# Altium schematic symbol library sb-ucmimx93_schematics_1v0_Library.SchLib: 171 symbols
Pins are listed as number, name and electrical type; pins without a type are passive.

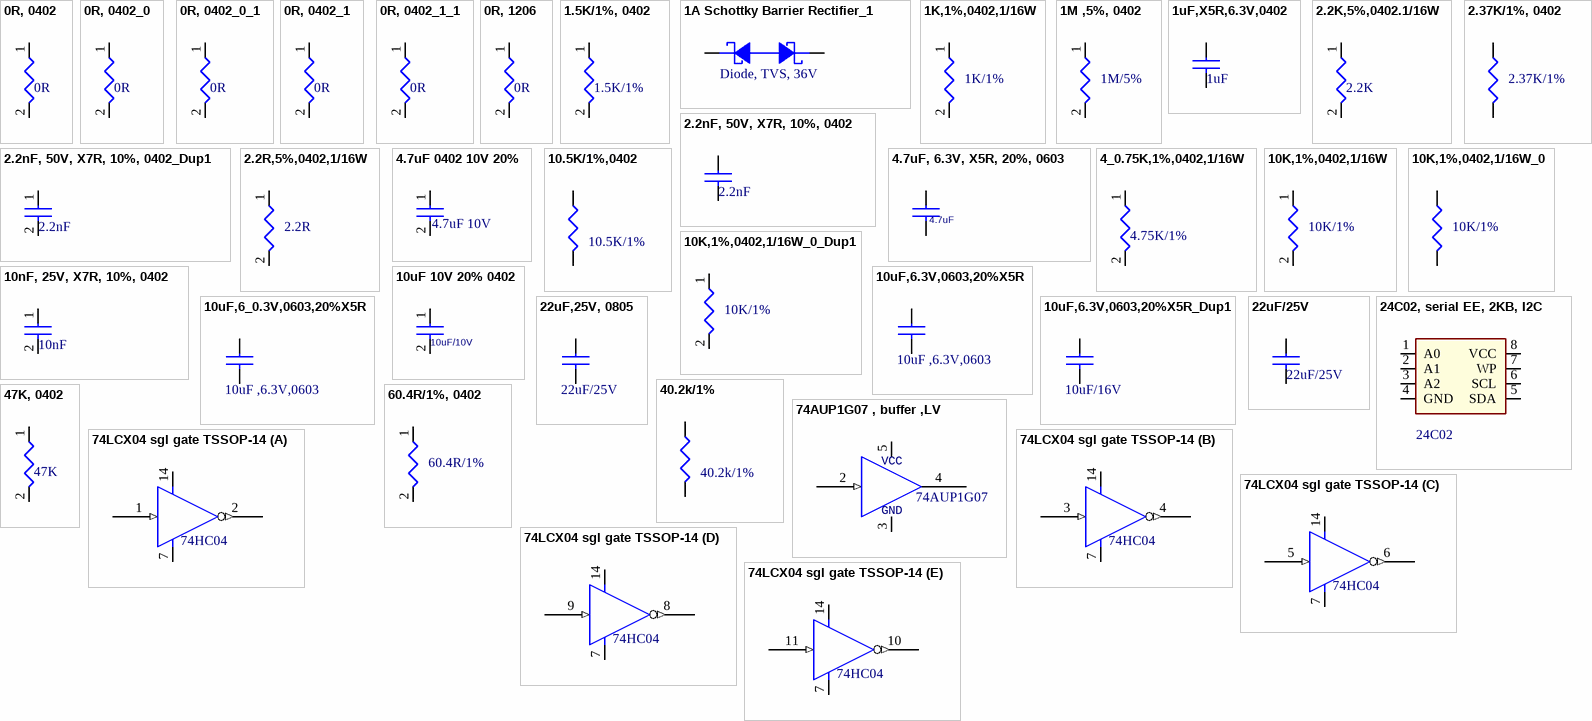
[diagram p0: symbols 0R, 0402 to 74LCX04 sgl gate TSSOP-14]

## 0R, 0402
designator R?, comment 0R
P/N: 161C00005S
footprint RC0402
pins: 1, 2

## 0R, 0402_0
designator R?, comment 0R
P/N: 161C00005S
footprint RC0402
pins: 1, 2

## 0R, 0402_0_1
designator R?, comment 0R
P/N: 161C00005S
footprint RC0402
pins: 1, 2

## 0R, 0402_1
designator R?, comment 0R
P/N: 161C00005S
footprint RC0402
pins: 1, 2

## 0R, 0402_1_1
designator R?, comment 0R
P/N: 161C00005S
footprint RC0402
pins: 1, 2

## 0R, 1206
designator R?, comment 0R
P/N: 161F00005S
footprint RC1206
pins: 1, 2

## 1.5K/1%, 0402
designator R?, comment 1.5K/1%
P/N: 161C15011S
footprint RC0402
pins: 1, 2

## 1A Schottky Barrier Rectifier_1
designator D?, comment Diode, TVS, 36V
P/N: 130E13000S
footprint SOD-123
pins: ANODE, CATHODE

## 1K,1%,0402,1/16W
designator R?, comment 1K/1%
P/N: 161C10011S
footprint RC0402
pins: 1, 2

## 1M ,5%, 0402
designator R?, comment 1M/5%
P/N: 161C10045S
pins: 1, 2

## 1uF,X5R,6.3V,0402
designator C?, comment 1uF
P/N: 151B10500S
footprint RC0402
pins: 1, 2

## 2.2K,5%,0402.1/16W
designator R?, comment 2.2K
P/N: 161C22015S
pins: 1, 2

## 2.2nF, 50V, X7R, 10%, 0402
designator C?, comment 2.2nF
P/N: 151D22200S
footprint RC0402
pins: 1, 2

## 2.2nF, 50V, X7R, 10%, 0402_Dup1
designator C?, comment 2.2nF
P/N: 151D22200S
footprint RC0402
pins: 1, 2

## 2.2R,5%,0402,1/16W
designator R?, comment 2.2R
P/N: 161C2R205S
footprint RC0402
pins: 1, 2

## 2.37K/1%, 0402
designator R?, comment 2.37K/1%
P/N: 161C23711S
footprint RC0402
pins: 1, 2

## 4.7uF 0402 10V 20%
designator C?, comment 4.7uF 10V
P/N: 151B47500S
footprint 0402
pins: 1, 2

## 4.7uF, 6.3V, X5R, 20%, 0603
designator C?, comment 4.7uF
P/N: 151B47510S
footprint C0603-08
pins: 1, 2

## 4_0.75K,1%,0402,1/16W
designator R?, comment 4.75K/1%
P/N: 161C47511S
footprint RC0402
pins: 1, 2

## 10.5K/1%,0402
designator R?, comment 10.5K/1%
P/N: 161C10521S
footprint RC0402
pins: 1, 2

## 10K,1%,0402,1/16W
designator R?, comment 10K/1%
P/N: 161C10021S
footprint RC0402
pins: 1, 2

## 10K,1%,0402,1/16W_0
designator R?, comment 10K/1%
P/N: 161C10021S
footprint RC0402
pins: 1, 2

## 10K,1%,0402,1/16W_0_Dup1
designator R?, comment 10K/1%
P/N: 161C10021S
footprint RC0402
pins: 1, 2

## 10nF, 25V, X7R, 10%, 0402
designator C?, comment 10nF
P/N: 151C10300S
footprint RC0402
pins: 1, 2

## 10uF 10V 20% 0402
designator C?, comment 10uF/10V
OriginalSymbolOrigin: (0,0); P/N: 151B10600S
footprint 0402
pins: 1, 2

## 10uF,6.3V,0603,20%X5R
designator C?, comment 10uF ,6.3V,0603
P/N: 151B10610S
footprint RC0603
pins: 1, 2

## 10uF,6.3V,0603,20%X5R_Dup1
designator C?, comment 10uF/16V
P/N: 151C10610S
footprint RC0603
pins: 1, 2

## 10uF,6_0.3V,0603,20%X5R
designator C?, comment 10uF ,6.3V,0603
P/N: 151B10610S
footprint RC0603
pins: 1, 2

## 22uF,25V, 0805
designator C?, comment 22uF/25V
P/N: 151C22620S
footprint C0805
pins: 1, 2

## 22uF/25V
designator C?
P/N: 151C22620S
footprint C0805
pins: 1, 2

## 24C02, serial EE, 2KB, I2C
designator U?, comment 24C02
P/N: 111S30800S
footprint MO-229VCED-2
pins: 1 A0, 2 A1, 3 A2, 4 GND, 5 SDA, 6 SCL, 7 WP, 8 VCC

## 40.2k/1%
designator R?
P/N: 161C40221S
footprint RC0402
pins: 1, 2

## 47K, 0402
designator R?, comment 47K
P/N: 161C47025S
footprint RC0402
pins: 1, 2

## 60.4R/1%, 0402
designator R?, comment 60.4R/1%
P/N: 161C60R41S
footprint RC0402
pins: 1, 2

## 74AUP1G07 , buffer ,LV
designator U?, comment 74AUP1G07
P/N: 106D20071S
footprint SC70
pins: 2 IN (in), 3 GND (power), 4 OUT (oc), 5 VCC (power)

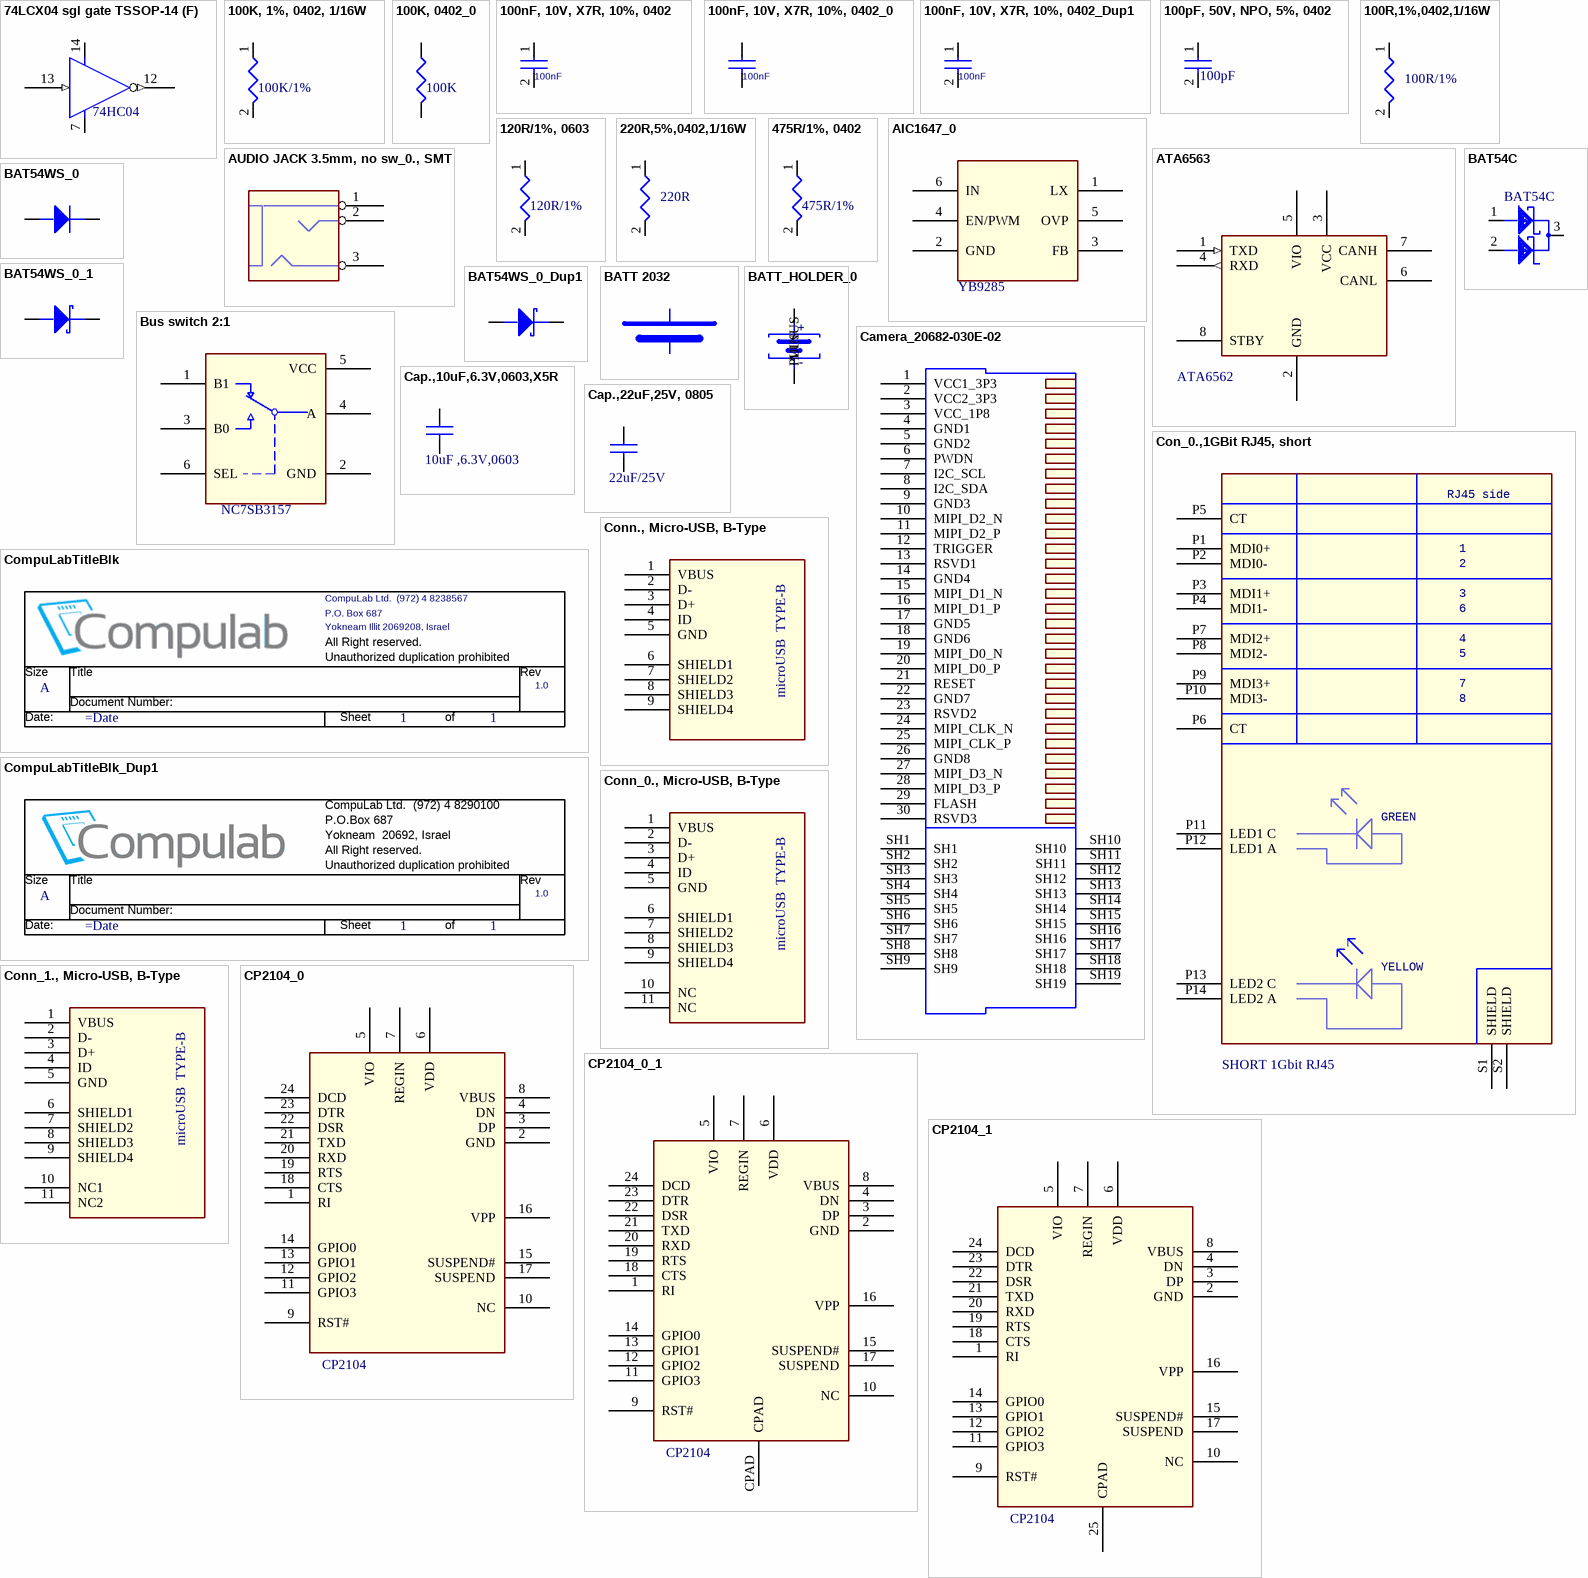
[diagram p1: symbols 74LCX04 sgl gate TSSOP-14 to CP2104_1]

## 74LCX04 sgl gate TSSOP-14
designator U?, comment 74HC04
P/N: 106D30040S
footprint TSSOP-14
part A pins: 1 I (in), 2 12 (out), 7 GND (power), 14 VCC (power)
part B pins: 3 I (in), 4 12 (out), 7 GND (power), 14 VCC (power)
part C pins: 5 I (in), 6 12 (out), 7 GND (power), 14 VCC (power)
part D pins: 7 GND (power), 8 12 (out), 9 I (in), 14 VCC (power)
part E pins: 7 GND (power), 10 12 (out), 11 I (in), 14 VCC (power)
part F pins: 7 GND (power), 12 (out), 13 I (in), 14 VCC (power)
1 alternate drawing of the same symbol

## 100K, 1%, 0402, 1/16W
designator R?, comment 100K/1%
P/N: 161C10031S
footprint RC0402
pins: 1, 2

## 100K, 0402_0
designator R?, comment 100K
P/N: 161C10035S
footprint RC0402
pins: 1, 2

## 100nF, 10V, X7R, 10%, 0402
designator C?, comment 100nF
P/N: 151B10400S
footprint RC0402
pins: 1, 2

## 100nF, 10V, X7R, 10%, 0402_0
designator C?, comment 100nF
P/N: 151B10400S
footprint RC0402
pins: 1, 2

## 100nF, 10V, X7R, 10%, 0402_Dup1
designator C?, comment 100nF
P/N: 151B10400S
footprint RC0402
pins: 1, 2

## 100pF, 50V, NPO, 5%, 0402
designator C?, comment 100pF
P/N: 151D10100S
footprint RC0402
pins: 1, 2

## 100R,1%,0402,1/16W
designator R?, comment 100R/1%
P/N: 161C10001S
footprint RC0402
pins: 1, 2

## 120R/1%, 0603
designator R?, comment 120R/1%
P/N: 161D12001S
footprint RC0603
pins: 1, 2

## 220R,5%,0402,1/16W
designator R?, comment 220R
P/N: 161C22005S
footprint RC0402
pins: 1, 2

## 475R/1%, 0402
designator R?, comment 475R/1%
P/N: 161C47501S
footprint RC0402
pins: 1, 2

## AIC1647_0
designator U?, comment YB9285
P/N: 123C20000S
footprint SOT23-5
pins: 1 LX, 2 GND, 3 FB, 4 EN/PWM, 5 OVP, 6 IN

## ATA6563
designator U?, comment ATA6562
P/N: 116A10500S
pins: 1 TXD (in), 2 GND (power), 3 VCC (power), 4 RXD (out), 5 VIO (power), 6 CANL, 7 CANH, 8 STBY

## AUDIO JACK 3.5mm, no sw_0., SMT
designator J?
P/N: 182K00300S
footprint AJ35-3P-SM
pins: 1 COM, 2 L, 3 R

## BAT54C
designator D?
P/N: 130E05400S
footprint SOT23
pins: 1 ANODE1, 2 ANODE2, 3 CATHODE

## BAT54WS_0
designator D?
P/N: 130E05402S
footprint SOD-323
pins: ANODE, CATHODE

## BAT54WS_0_1
designator D?
P/N: 130E05402S
footprint SOD-323
pins: ANODE, CATHODE

## BAT54WS_0_Dup1
designator D?
P/N: 130E05402S
footprint SOD-323
pins: ANODE, CATHODE

## BATT 2032
designator BT?
P/N: 210C30002

## BATT_HOLDER_0
designator BH?
P/N: 190Z00201
footprint BATTH20MM
pins: 1 MINUS, 2 PLUS

## Bus switch 2:1
designator U?, comment NC7SB3157
P/N: 124S10050S
footprint SC70-6
pins: 1 B1, 2 GND, 3 B0, 4 A, 5 VCC, 6 SEL

## Camera_20682-030E-02
designator P?
P/N: 182P04000S
pins: 1 VCC1_3P3, 2 VCC2_3P3, 3 VCC_1P8, 4 GND1, 5 GND2, 6 PWDN, 7 I2C_SCL, 8 I2C_SDA, 9 GND3, 10 MIPI_D2_N, 11 MIPI_D2_P, 12 TRIGGER, 13 RSVD1, 14 GND4, 15 MIPI_D1_N, 16 MIPI_D1_P, 17 GND5, 18 GND6, 19 MIPI_D0_N, 20 MIPI_D0_P, 21 RESET, 22 GND7, 23 RSVD2, 24 MIPI_CLK_N, 25 MIPI_CLK_P, 26 GND8, 27 MIPI_D3_N, 28 MIPI_D3_P, 29 FLASH, 30 RSVD3, SH1, SH2, SH3, SH4, SH5, SH6, SH7, SH8, SH9, SH10, SH11, SH12, SH13, SH14, SH15, SH16, SH17, SH18, SH19

## Cap.,10uF,6.3V,0603,X5R
designator C?, comment 10uF ,6.3V,0603
P/N: 151B10610S
footprint RC0603
pins: 1, 2

## Cap.,22uF,25V, 0805
designator C?, comment 22uF/25V
P/N: 151C22620S
footprint C0805
pins: 1, 2

## CompuLabTitleBlk
designator *  RevCode: 1.0  OrgName: CompuLab Ltd.  (972) 4 8238567  OrgAddr1: P.O. Box 687  OrgAddr2: Yokneam Illit 2069208, Israel  Page Size: A  Page Number: 1  (hidden comment: *)  (graphical)

## CompuLabTitleBlk_Dup1
designator *  RevCode: 1.0  Page Size: A  Page Number: 1  (hidden comment: *)  (graphical)
OrgName: CompuLab Ltd.  (972) 4 8238567; OrgAddr1: P.O.Box 66; OrgAddr2: Nesher 36770, Israel

## Con_0.,1GBit RJ45, short
designator P?, comment SHORT 1Gbit RJ45
P/N: 182K01600
footprint RJTR1GRATH
pins: P1 MDI0+, P2 MDI0-, P3 MDI1+, P4 MDI1-, P5 CT, P6 CT, P7 MDI2+, P8 MDI2-, P9 MDI3+, P10 MDI3-, P11 LED1 C, P12 LED1 A, P13 LED2 C, P14 LED2 A, S1 SHIELD (power), S2 SHIELD (power)

## Conn., Micro-USB, B-Type
designator P?, comment microUSB  TYPE-B
P/N: 180K00501S
footprint MICRO-USB-B-RA-SM
pins: 1 VBUS, 2 D-, 3 D+, 4 ID, 5 GND, 6 SHIELD1, 7 SHIELD2, 8 SHIELD3, 9 SHIELD4

## Conn_0., Micro-USB, B-Type
designator P?, comment microUSB  TYPE-B
P/N: 180K00501S
footprint MICRO-USB-B-RA-SM
pins: 1 VBUS, 2 D-, 3 D+, 4 ID, 5 GND, 6 SHIELD1, 7 SHIELD2, 8 SHIELD3, 9 SHIELD4, 10 NC, 11 NC

## Conn_1., Micro-USB, B-Type
designator P?, comment microUSB  TYPE-B
P/N: 180K00501S
footprint MICRO-USB-B-RA-SM
pins: 1 VBUS, 2 D-, 3 D+, 4 ID, 5 GND, 6 SHIELD1, 7 SHIELD2, 8 SHIELD3, 9 SHIELD4, 10 NC1, 11 NC2

## CP2104_0
designator U?, comment CP2104
pins: 1 RI, 2 GND, 3 DP, 4 DN, 5 VIO, 6 VDD, 7 REGIN, 8 VBUS, 9 RST#, 10 NC, 11 GPIO3, 12 GPIO2, 13 GPIO1, 14 GPIO0, 15 SUSPEND#, 16 VPP, 17 SUSPEND, 18 CTS, 19 RTS, 20 RXD, 21 TXD, 22 DSR, 23 DTR, 24 DCD

## CP2104_0_1
designator U?, comment CP2104
pins: 1 RI, 2 GND, 3 DP, 4 DN, 5 VIO, 6 VDD, 7 REGIN, 8 VBUS, 9 RST#, 10 NC, 11 GPIO3, 12 GPIO2, 13 GPIO1, 14 GPIO0, 15 SUSPEND#, 16 VPP, 17 SUSPEND, 18 CTS, 19 RTS, 20 RXD, 21 TXD, 22 DSR, 23 DTR, 24 DCD, CPAD

## CP2104_1
designator U?, comment CP2104
pins: 1 RI, 2 GND, 3 DP, 4 DN, 5 VIO, 6 VDD, 7 REGIN, 8 VBUS, 9 RST#, 10 NC, 11 GPIO3, 12 GPIO2, 13 GPIO1, 14 GPIO0, 15 SUSPEND#, 16 VPP, 17 SUSPEND, 18 CTS, 19 RTS, 20 RXD, 21 TXD, 22 DSR, 23 DTR, 24 DCD, 25 CPAD

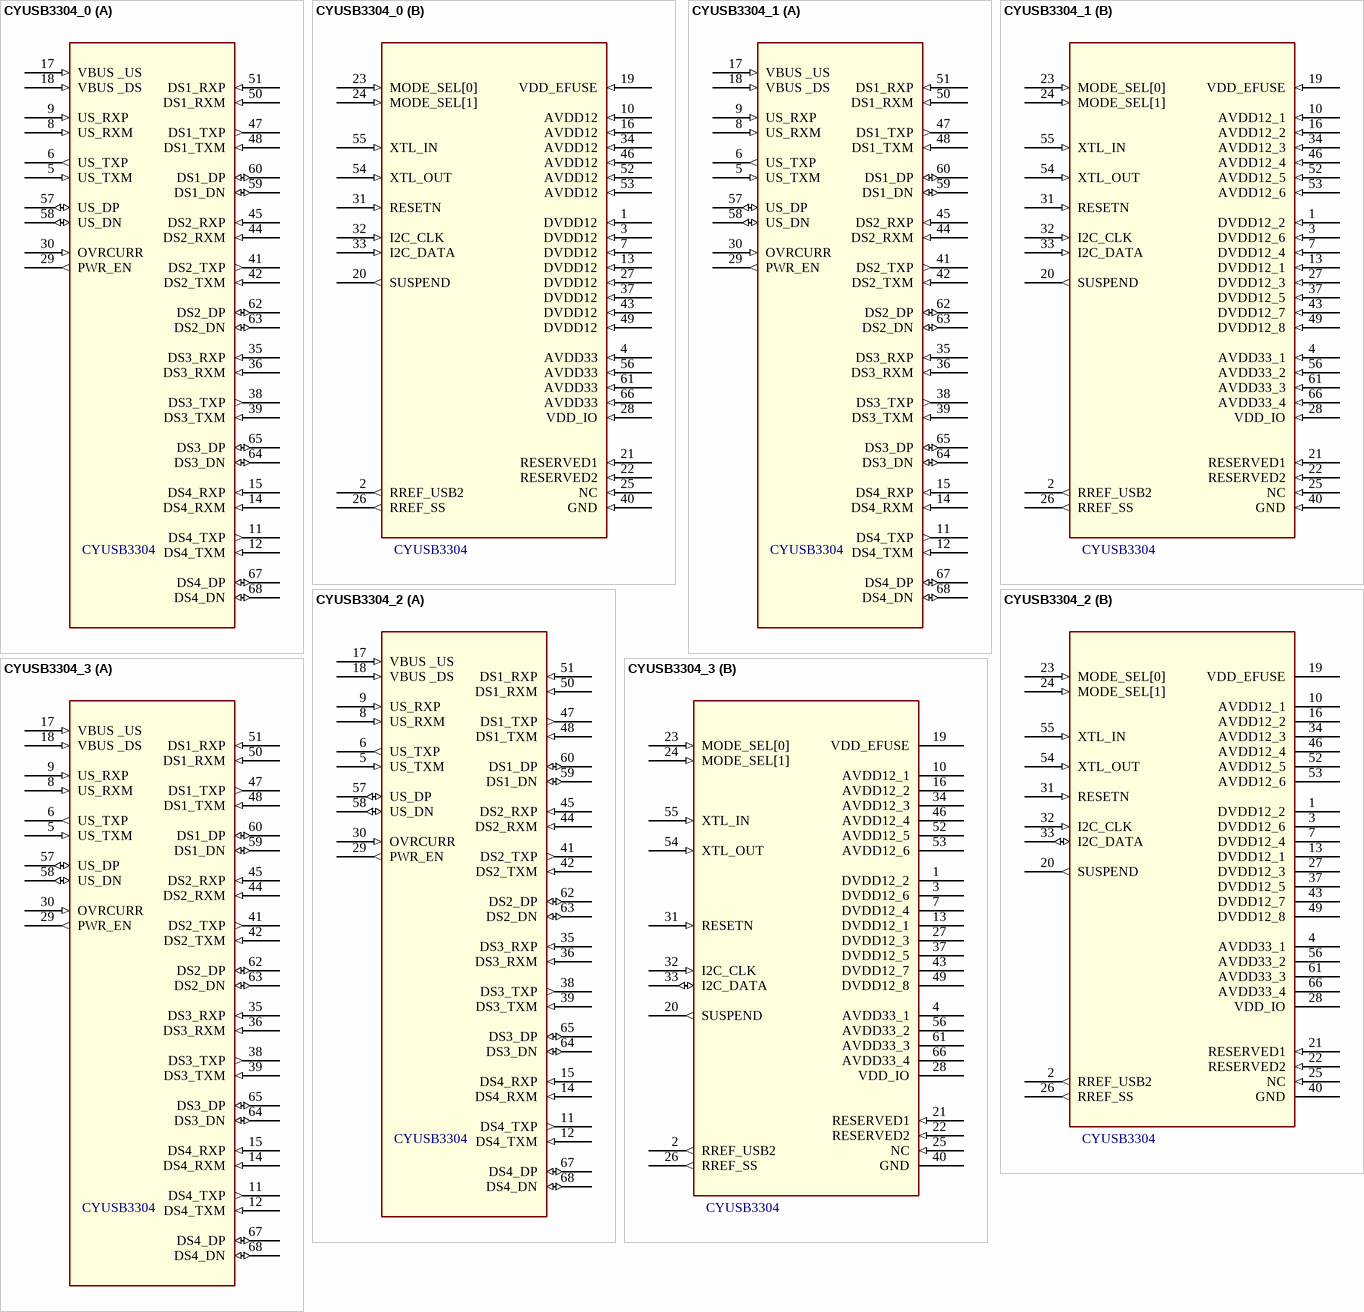
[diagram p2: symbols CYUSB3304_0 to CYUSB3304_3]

## CYUSB3304_0
designator U?, comment CYUSB3304
part A pins: 5 US_TXM (in), 6 US_TXP (out), 8 US_RXM (in), 9 US_RXP (in), 11 DS4_TXP (out), 12 DS4_TXM (in), 14 DS4_RXM (in), 15 DS4_RXP (in), 17 VBUS _US (in), 18 VBUS _DS (in), 29 PWR_EN (out), 30 OVRCURR (in), 35 DS3_RXP (in), 36 DS3_RXM (in), 38 DS3_TXP (out), 39 DS3_TXM (in), 41 DS2_TXP (out), 42 DS2_TXM (in), 44 DS2_RXM (in), 45 DS2_RXP (in), 47 DS1_TXP (out), 48 DS1_TXM (in), 50 DS1_RXM (in), 51 DS1_RXP (in), 57 US_DP (io), 58 US_DN (io), 59 DS1_DN (io), 60 DS1_DP (io), 62 DS2_DP (io), 63 DS2_DN (io), 64 DS3_DN (io), 65 DS3_DP (io), 67 DS4_DP (io), 68 DS4_DN (io)
part B pins: 1 DVDD12 (in), 2 RREF_USB2 (out), 3 DVDD12 (in), 4 AVDD33 (in), 7 DVDD12 (in), 10 AVDD12 (in), 13 DVDD12 (in), 16 AVDD12 (in), 19 VDD_EFUSE (in), 20 SUSPEND (out), 21 RESERVED1 (in), 22 RESERVED2 (in), 23 MODE_SEL[0] (in), 24 MODE_SEL[1] (in), 25 NC (in), 26 RREF_SS (out), 27 DVDD12 (in), 28 VDD_IO (in), 31 RESETN (in), 32 I2C_CLK (in), 33 I2C_DATA (in), 34 AVDD12 (in), 37 DVDD12 (in), 40 GND (in), 43 DVDD12 (in), 46 AVDD12 (in), 49 DVDD12 (in), 52 AVDD12 (in), 53 AVDD12 (in), 54 XTL_OUT (in), 55 XTL_IN (in), 56 AVDD33 (in), 61 AVDD33 (in), 66 AVDD33 (in)

## CYUSB3304_1
designator U?, comment CYUSB3304
part A pins: 5 US_TXM (in), 6 US_TXP (out), 8 US_RXM (in), 9 US_RXP (in), 11 DS4_TXP (out), 12 DS4_TXM (in), 14 DS4_RXM (in), 15 DS4_RXP (in), 17 VBUS _US (in), 18 VBUS _DS (in), 29 PWR_EN (out), 30 OVRCURR (in), 35 DS3_RXP (in), 36 DS3_RXM (in), 38 DS3_TXP (out), 39 DS3_TXM (in), 41 DS2_TXP (out), 42 DS2_TXM (in), 44 DS2_RXM (in), 45 DS2_RXP (in), 47 DS1_TXP (out), 48 DS1_TXM (in), 50 DS1_RXM (in), 51 DS1_RXP (in), 57 US_DP (io), 58 US_DN (io), 59 DS1_DN (io), 60 DS1_DP (io), 62 DS2_DP (io), 63 DS2_DN (io), 64 DS3_DN (io), 65 DS3_DP (io), 67 DS4_DP (io), 68 DS4_DN (io)
part B pins: 1 DVDD12_2 (in), 2 RREF_USB2 (out), 3 DVDD12_6 (in), 4 AVDD33_1 (in), 7 DVDD12_4 (in), 10 AVDD12_1 (in), 13 DVDD12_1 (in), 16 AVDD12_2 (in), 19 VDD_EFUSE (in), 20 SUSPEND (out), 21 RESERVED1 (in), 22 RESERVED2 (in), 23 MODE_SEL[0] (in), 24 MODE_SEL[1] (in), 25 NC (in), 26 RREF_SS (out), 27 DVDD12_3 (in), 28 VDD_IO (in), 31 RESETN (in), 32 I2C_CLK (in), 33 I2C_DATA (in), 34 AVDD12_3 (in), 37 DVDD12_5 (in), 40 GND (in), 43 DVDD12_7 (in), 46 AVDD12_4 (in), 49 DVDD12_8 (in), 52 AVDD12_5 (in), 53 AVDD12_6 (in), 54 XTL_OUT (in), 55 XTL_IN (in), 56 AVDD33_2 (in), 61 AVDD33_3 (in), 66 AVDD33_4 (in)

## CYUSB3304_2
designator U?, comment CYUSB3304
part A pins: 5 US_TXM (in), 6 US_TXP (out), 8 US_RXM (in), 9 US_RXP (in), 11 DS4_TXP (out), 12 DS4_TXM (in), 14 DS4_RXM (in), 15 DS4_RXP (in), 17 VBUS _US (in), 18 VBUS _DS (in), 29 PWR_EN (out), 30 OVRCURR (in), 35 DS3_RXP (in), 36 DS3_RXM (in), 38 DS3_TXP (out), 39 DS3_TXM (in), 41 DS2_TXP (out), 42 DS2_TXM (in), 44 DS2_RXM (in), 45 DS2_RXP (in), 47 DS1_TXP (out), 48 DS1_TXM (in), 50 DS1_RXM (in), 51 DS1_RXP (in), 57 US_DP (io), 58 US_DN (io), 59 DS1_DN (io), 60 DS1_DP (io), 62 DS2_DP (io), 63 DS2_DN (io), 64 DS3_DN (io), 65 DS3_DP (io), 67 DS4_DP (io), 68 DS4_DN (io)
part B pins: 1 DVDD12_2 (power), 2 RREF_USB2 (out), 3 DVDD12_6 (power), 4 AVDD33_1 (power), 7 DVDD12_4 (power), 10 AVDD12_1 (power), 13 DVDD12_1 (power), 16 AVDD12_2 (power), 19 VDD_EFUSE (power), 20 SUSPEND (out), 21 RESERVED1 (in), 22 RESERVED2 (in), 23 MODE_SEL[0] (in), 24 MODE_SEL[1] (in), 25 NC (in), 26 RREF_SS (out), 27 DVDD12_3 (power), 28 VDD_IO (power), 31 RESETN (in), 32 I2C_CLK (in), 33 I2C_DATA (io), 34 AVDD12_3 (power), 37 DVDD12_5 (power), 40 GND (power), 43 DVDD12_7 (power), 46 AVDD12_4 (power), 49 DVDD12_8 (power), 52 AVDD12_5 (power), 53 AVDD12_6 (power), 54 XTL_OUT (in), 55 XTL_IN (in), 56 AVDD33_2 (power), 61 AVDD33_3 (power), 66 AVDD33_4 (power)

## CYUSB3304_3
designator U?, comment CYUSB3304
part A pins: 5 US_TXM (in), 6 US_TXP (out), 8 US_RXM (in), 9 US_RXP (in), 11 DS4_TXP (out), 12 DS4_TXM (in), 14 DS4_RXM (in), 15 DS4_RXP (in), 17 VBUS _US (in), 18 VBUS _DS (in), 29 PWR_EN (out), 30 OVRCURR (in), 35 DS3_RXP (in), 36 DS3_RXM (in), 38 DS3_TXP (out), 39 DS3_TXM (in), 41 DS2_TXP (out), 42 DS2_TXM (in), 44 DS2_RXM (in), 45 DS2_RXP (in), 47 DS1_TXP (out), 48 DS1_TXM (in), 50 DS1_RXM (in), 51 DS1_RXP (in), 57 US_DP (io), 58 US_DN (io), 59 DS1_DN (io), 60 DS1_DP (io), 62 DS2_DP (io), 63 DS2_DN (io), 64 DS3_DN (io), 65 DS3_DP (io), 67 DS4_DP (io), 68 DS4_DN (io)
part B pins: 1 DVDD12_2 (power), 2 RREF_USB2 (out), 3 DVDD12_6 (power), 4 AVDD33_1 (power), 7 DVDD12_4 (power), 10 AVDD12_1 (power), 13 DVDD12_1 (power), 16 AVDD12_2 (power), 19 VDD_EFUSE (power), 20 SUSPEND (out), 21 RESERVED1 (in), 22 RESERVED2 (in), 23 MODE_SEL[0] (in), 24 MODE_SEL[1] (in), 25 NC (in), 26 RREF_SS (out), 27 DVDD12_3 (power), 28 VDD_IO (power), 31 RESETN (in), 32 I2C_CLK (in), 33 I2C_DATA (io), 34 AVDD12_3 (power), 37 DVDD12_5 (power), 40 GND (power), 43 DVDD12_7 (power), 46 AVDD12_4 (power), 49 DVDD12_8 (power), 52 AVDD12_5 (power), 53 AVDD12_6 (power), 54 XTL_OUT (in), 55 XTL_IN (in), 56 AVDD33_2 (power), 61 AVDD33_3 (power), 66 AVDD33_4 (power)

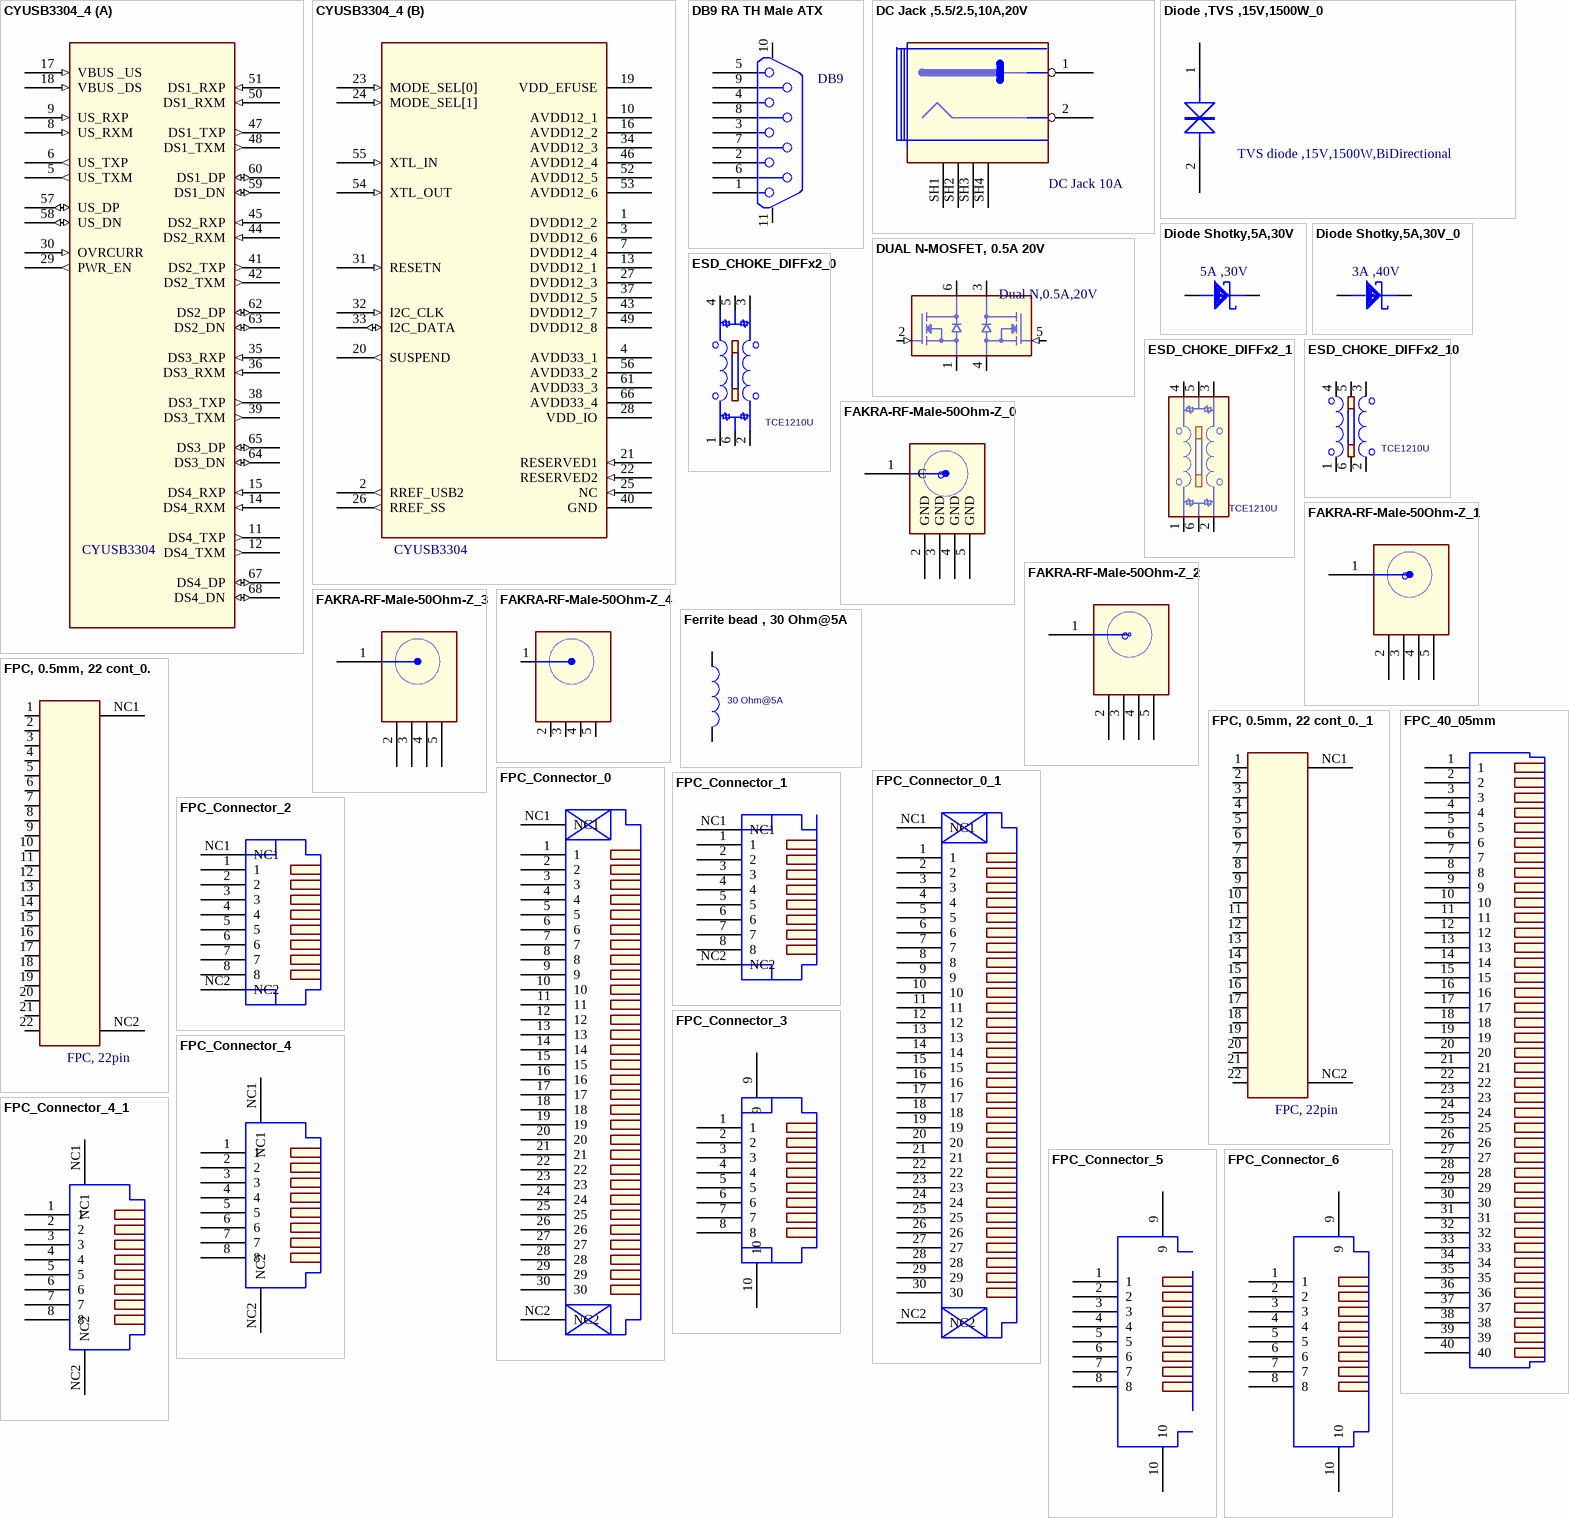
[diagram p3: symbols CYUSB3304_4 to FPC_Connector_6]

## CYUSB3304_4
designator U?, comment CYUSB3304
part A pins: 5 US_TXM (out), 6 US_TXP (out), 8 US_RXM (in), 9 US_RXP (in), 11 DS4_TXP (out), 12 DS4_TXM (out), 14 DS4_RXM (in), 15 DS4_RXP (in), 17 VBUS _US (in), 18 VBUS _DS (in), 29 PWR_EN (out), 30 OVRCURR (in), 35 DS3_RXP (in), 36 DS3_RXM (in), 38 DS3_TXP (out), 39 DS3_TXM (out), 41 DS2_TXP (out), 42 DS2_TXM (out), 44 DS2_RXM (in), 45 DS2_RXP (in), 47 DS1_TXP (out), 48 DS1_TXM (out), 50 DS1_RXM (in), 51 DS1_RXP (in), 57 US_DP (io), 58 US_DN (io), 59 DS1_DN (io), 60 DS1_DP (io), 62 DS2_DP (io), 63 DS2_DN (io), 64 DS3_DN (io), 65 DS3_DP (io), 67 DS4_DP (io), 68 DS4_DN (io)
part B pins: 1 DVDD12_2 (power), 2 RREF_USB2 (out), 3 DVDD12_6 (power), 4 AVDD33_1 (power), 7 DVDD12_4 (power), 10 AVDD12_1 (power), 13 DVDD12_1 (power), 16 AVDD12_2 (power), 19 VDD_EFUSE (power), 20 SUSPEND (out), 21 RESERVED1 (in), 22 RESERVED2 (in), 23 MODE_SEL[0] (in), 24 MODE_SEL[1] (in), 25 NC (in), 26 RREF_SS (out), 27 DVDD12_3 (power), 28 VDD_IO (power), 31 RESETN (in), 32 I2C_CLK (in), 33 I2C_DATA (io), 34 AVDD12_3 (power), 37 DVDD12_5 (power), 40 GND (power), 43 DVDD12_7 (power), 46 AVDD12_4 (power), 49 DVDD12_8 (power), 52 AVDD12_5 (power), 53 AVDD12_6 (power), 54 XTL_OUT (in), 55 XTL_IN (in), 56 AVDD33_2 (power), 61 AVDD33_3 (power), 66 AVDD33_4 (power)

## DB9 RA TH Male ATX
designator P?, comment DB9
P/N: 180K00901
footprint DB9RATH
pins: 1, 2, 3, 4, 5, 6, 7, 8, 9, 10 BRACKET, 11 BRACKET

## DC Jack ,5.5/2.5,10A,20V
designator J?, comment DC Jack 10A
P/N: 180K00200
footprint PJ-0810-TH
pins: 1 CENTRAL, 2 R, SH1, SH2, SH3, SH4

## Diode ,TVS ,15V,1500W_0
designator D?, comment TVS diode ,15V,1500W,BiDirectional
P/N: TMP_TVS
footprint DO-214AB
pins: 1, 2

## Diode Shotky,5A,30V
designator D?, comment 5A ,30V
P/N: 130E30001S
footprint SOD-128
pins: ANODE, CATHODE

## Diode Shotky,5A,30V_0
designator D?, comment 3A ,40V
P/N: 130E30001S
footprint SOD-128
pins: ANODE, CATHODE

## DUAL N-MOSFET, 0.5A 20V
designator Q?, comment Dual N,0.5A,20V
P/N: 131D31540S
footprint SOT-563-6
pins: 1 S1, 2 G1 (in), 3 D2, 4 S2, 5 G2 (in), 6 D1

## ESD_CHOKE_DIFFx2_0
designator L?, comment TCE1210U
P/N: tmp_ESD_CHOKE
footprint 0805
pins: 1, 2, 3, 4, 5 GND (power), 6 GND (power)

## ESD_CHOKE_DIFFx2_1
designator L?, comment TCE1210U
P/N: tmp_ESD_CHOKE
footprint 0805
pins: 1, 2, 3, 4, 5 GND (power), 6 GND (power)

## ESD_CHOKE_DIFFx2_10
designator L?, comment TCE1210U
P/N: tmp_ESD_CHOKE
footprint 0805
pins: 1, 2, 3, 4, 5 GND (power), 6 GND (power)

## FAKRA-RF-Male-50Ohm-Z_0
designator J?
P/N: 182E00402
footprint SMB-JACK
pins: 1 C, 2 GND, 3 GND, 4 GND, 5 GND

## FAKRA-RF-Male-50Ohm-Z_1
designator J?
P/N: 182E00402
footprint SMB-JACK
pins: 1 C, 2 GND, 3 GND, 4 GND, 5 GND

## FAKRA-RF-Male-50Ohm-Z_2
designator J?
P/N: 182E00402
footprint SMB-JACK
pins: 1 C, 2 GND, 3 GND, 4 GND, 5 GND

## FAKRA-RF-Male-50Ohm-Z_3
designator J?
P/N: 182E00402
footprint SMB-JACK
pins: 1 C, 2 GND, 3 GND, 4 GND, 5 GND

## FAKRA-RF-Male-50Ohm-Z_4
designator J?
P/N: 182E00402
footprint SMB-JACK
pins: 1 C, 2 GND, 3 GND, 4 GND, 5 GND

## Ferrite bead , 30 Ohm@5A
designator FB?, comment 30 Ohm@5A
P/N: 147D30000S
footprint FB0603
pins: 1, 2

## FPC, 0.5mm, 22 cont_0.
designator P?, comment FPC, 22pin
P/N: 182P02200S
footprint FPC05SM22
pins: 1, 2, 3, 4, 5, 6, 7, 8, 9, 10, 11, 12, 13, 14, 15, 16, 17, 18, 19, 20, 21, 22, NC1, NC2

## FPC, 0.5mm, 22 cont_0._1
designator P?, comment FPC, 22pin
P/N: 182P02200S
footprint FPC05SM22
pins: 1, 2, 3, 4, 5, 6, 7, 8, 9, 10, 11, 12, 13, 14, 15, 16, 17, 18, 19, 20, 21, 22, NC1, NC2

## FPC_40_05mm
designator P?
P/N: 182P04000S
footprint FPC05SM40
pins: 1, 2, 3, 4, 5, 6, 7, 8, 9, 10, 11, 12, 13, 14, 15, 16, 17, 18, 19, 20, 21, 22, 23, 24, 25, 26, 27, 28, 29, 30, 31, 32, 33, 34, 35, 36, 37, 38, 39, 40

## FPC_Connector_0
designator J?
P/N: 182P04000S
footprint FPC_30
pins: 1, 2, 3, 4, 5, 6, 7, 8, 9, 10, 11, 12, 13, 14, 15, 16, 17, 18, 19, 20, 21, 22, 23, 24, 25, 26, 27, 28, 29, 30, NC1, NC2

## FPC_Connector_0_1
designator J?
P/N: 182P04000S
footprint FPC_30
pins: 1, 2, 3, 4, 5, 6, 7, 8, 9, 10, 11, 12, 13, 14, 15, 16, 17, 18, 19, 20, 21, 22, 23, 24, 25, 26, 27, 28, 29, 30, NC1, NC2

## FPC_Connector_1
designator P?
P/N: 182P04000S
footprint FPC_8
pins: 1, 2, 3, 4, 5, 6, 7, 8, NC1, NC2

## FPC_Connector_2
designator P?
P/N: 182P04000S
footprint FPC_8
pins: 1, 2, 3, 4, 5, 6, 7, 8, NC1, NC2

## FPC_Connector_3
designator P?
P/N: 182P04000S
footprint FPC_8
pins: 1, 2, 3, 4, 5, 6, 7, 8, 9, 10

## FPC_Connector_4
designator P?
P/N: 182P04000S
footprint FPC_8
pins: 1, 2, 3, 4, 5, 6, 7, 8, NC1, NC2

## FPC_Connector_4_1
designator P?
P/N: 182P04000S
footprint FPC_8
pins: 1, 2, 3, 4, 5, 6, 7, 8, NC1, NC2

## FPC_Connector_5
designator P?
P/N: 182P04000S
footprint FPC_8
pins: 1, 2, 3, 4, 5, 6, 7, 8, 9, 10

## FPC_Connector_6
designator P?
P/N: 182P04000S
footprint FPC_8
pins: 1, 2, 3, 4, 5, 6, 7, 8, 9, 10

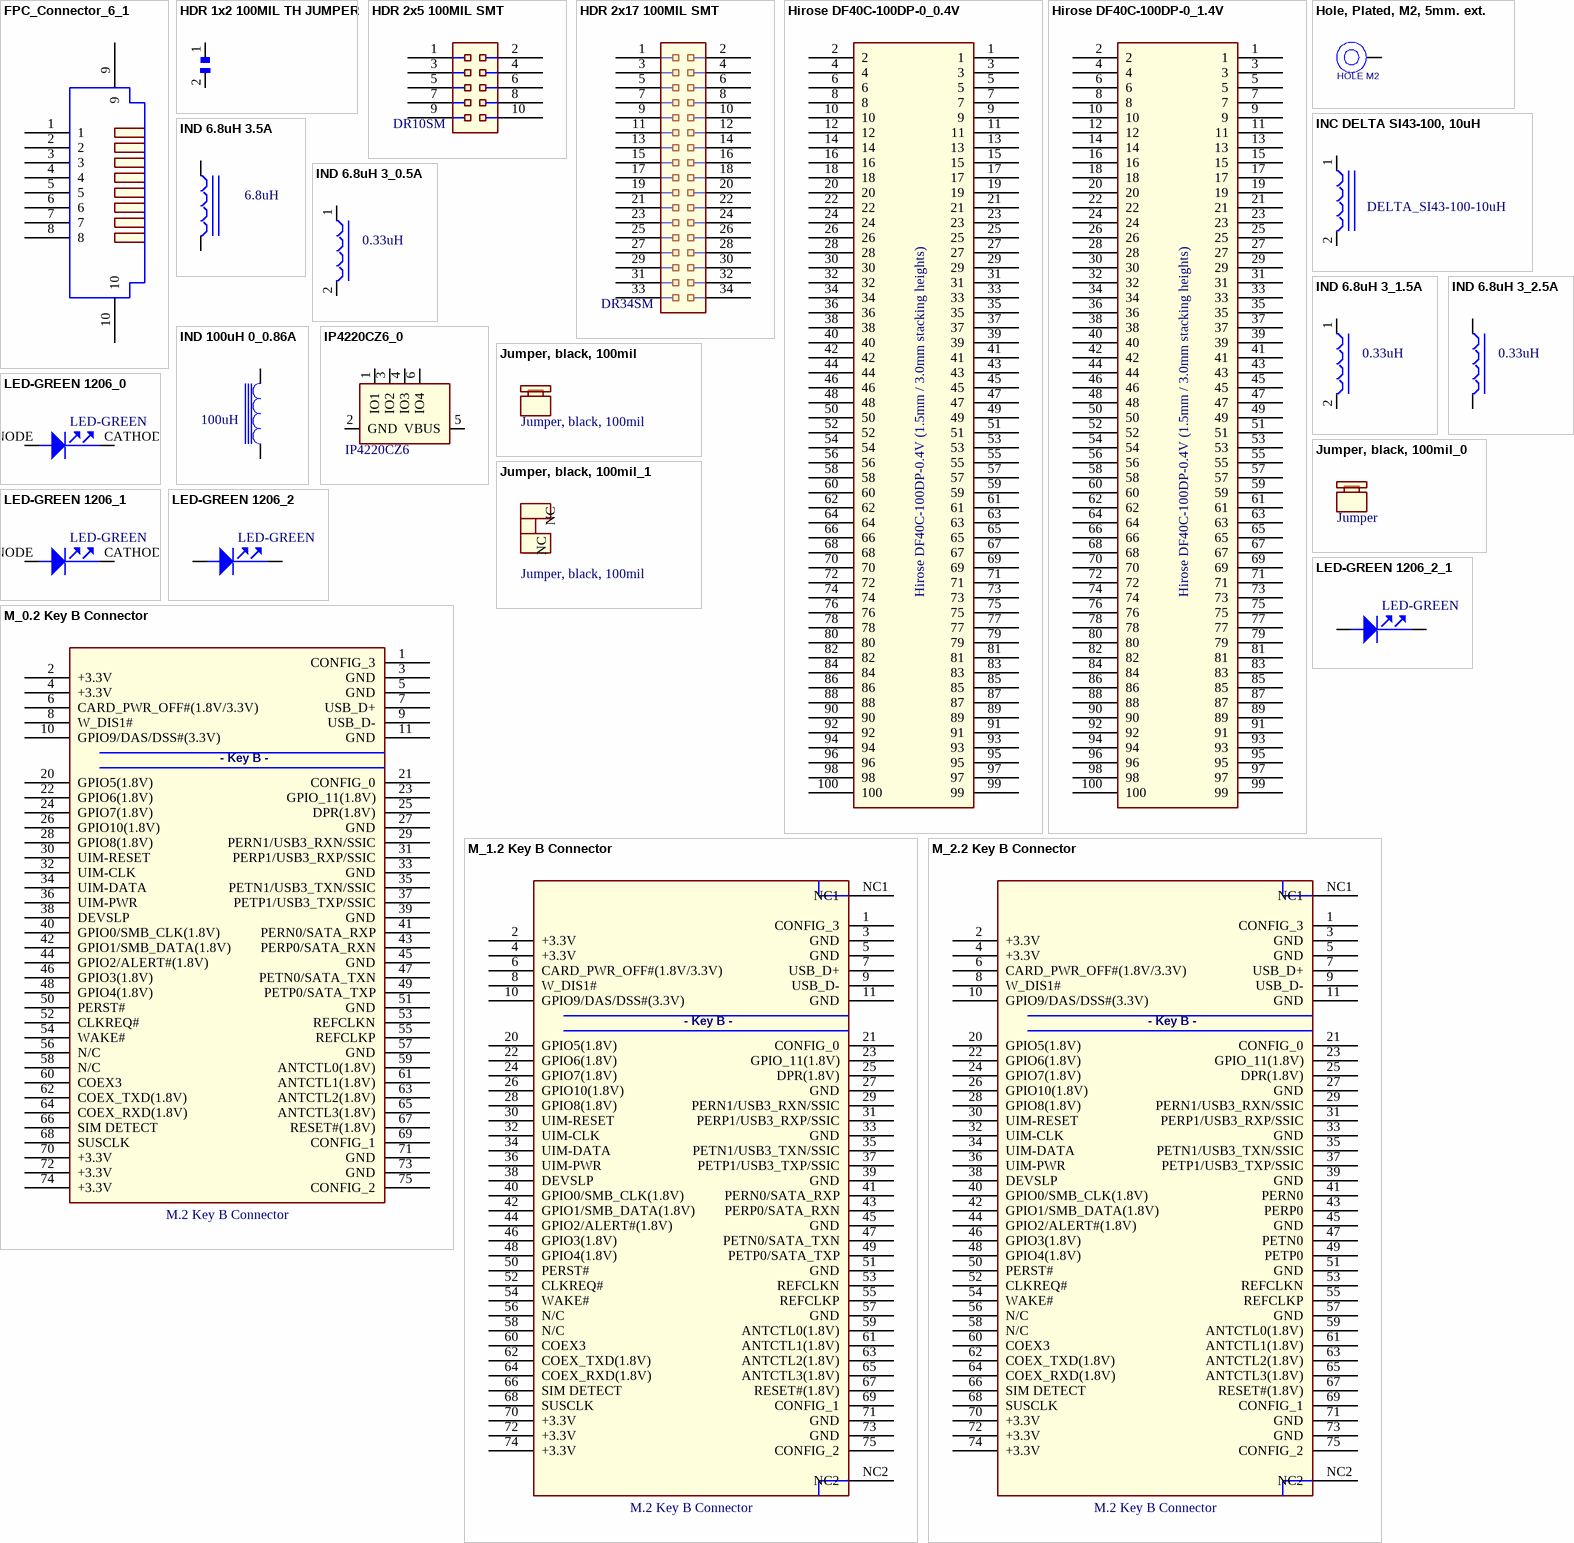
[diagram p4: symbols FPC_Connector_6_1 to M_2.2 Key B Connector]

## FPC_Connector_6_1
designator P?
P/N: 182P04000S
footprint FPC_8
pins: 1, 2, 3, 4, 5, 6, 7, 8, 9, 10

## HDR 1x2 100MIL TH JUMPER
designator E?, comment HDR1X2  (value not drawn)
P/N: 190C00200; PCB Footprint: TH_1x2_100MIL
footprint 1X2THHDR
pins: 1, 2

## HDR 2x5 100MIL SMT
designator P?, comment DR10SM
P/N: 190C01000S
footprint 2X5SMHDR
pins: 1, 2, 3, 4, 5, 6, 7, 8, 9, 10

## HDR 2x17 100MIL SMT
designator P?, comment DR34SM
P/N: 190C03400S
footprint 2X17SMHDR
pins: 1, 2, 3, 4, 5, 6, 7, 8, 9, 10, 11, 12, 13, 14, 15, 16, 17, 18, 19, 20, 21, 22, 23, 24, 25, 26, 27, 28, 29, 30, 31, 32, 33, 34

## Hirose DF40C-100DP-0_0.4V
designator P?, comment Hirose DF40C-100DP-0.4V (1.5mm / 3.0mm stacking heights)
pins: 1, 2, 3, 4, 5, 6, 7, 8, 9, 10, 11, 12, 13, 14, 15, 16, 17, 18, 19, 20, 21, 22, 23, 24, 25, 26, 27, 28, 29, 30, 31, 32, 33, 34, 35, 36, 37, 38, 39, 40, 41, 42, 43, 44, 45, 46, 47, 48, 49, 50, 51, 52, 53, 54, 55, 56, 57, 58, 59, 60, 61, 62, 63, 64, 65, 66, 67, 68, 69, 70, 71, 72, 73, 74, 75, 76, 77, 78, 79, 80, 81, 82, 83, 84, 85, 86, 87, 88, 89, 90, 91, 92, 93, 94, 95, 96, 97, 98, 99, 100

## Hirose DF40C-100DP-0_1.4V
designator P?, comment Hirose DF40C-100DP-0.4V (1.5mm / 3.0mm stacking heights)
pins: 1, 2, 3, 4, 5, 6, 7, 8, 9, 10, 11, 12, 13, 14, 15, 16, 17, 18, 19, 20, 21, 22, 23, 24, 25, 26, 27, 28, 29, 30, 31, 32, 33, 34, 35, 36, 37, 38, 39, 40, 41, 42, 43, 44, 45, 46, 47, 48, 49, 50, 51, 52, 53, 54, 55, 56, 57, 58, 59, 60, 61, 62, 63, 64, 65, 66, 67, 68, 69, 70, 71, 72, 73, 74, 75, 76, 77, 78, 79, 80, 81, 82, 83, 84, 85, 86, 87, 88, 89, 90, 91, 92, 93, 94, 95, 96, 97, 98, 99, 100

## Hole, Plated, M2, 5mm. ext.
designator H?, comment HOLE M2
P/N: 188Z10010
footprint M2PAD
pins: 1

## INC DELTA SI43-100, 10uH
designator L?, comment DELTA_SI43-100-10uH
P/N: 147A10001S
footprint IND4x4x2_5
pins: 1, 2

## IND 6.8uH 3.5A
designator L?, comment 6.8uH
pins: 1, 2

## IND 6.8uH 3_0.5A
designator L?, comment 0.33uH
pins: 1, 2

## IND 6.8uH 3_1.5A
designator L?, comment 0.33uH
pins: 1, 2

## IND 6.8uH 3_2.5A
designator L?, comment 0.33uH
pins: 1, 2

## IND 100uH 0_0.86A
designator L?, comment 100uH
P/N: 147A10100S; PCB Footprint: IND7_6x7_6x4_5
footprint IND9x9x4_5
pins: 1, 2

## IP4220CZ6_0
designator U?, comment IP4220CZ6
P/N: 132D42200S
footprint SOT23-6L
pins: 1 IO1, 2 GND, 3 IO2, 4 IO3, 5 VBUS, 6 IO4

## Jumper, black, 100mil
designator JP?
P/N: 185B10010

## Jumper, black, 100mil_0
designator JP?, comment Jumper
P/N: 185B10010

## Jumper, black, 100mil_1
designator JP?, comment Jumper, black, 100mil
P/N: 185B10010
pins: NC

## LED-GREEN 1206_0
designator DS?, comment LED-GREEN
P/N: 139A10020S
footprint LED-1206
pins: ANODE, CATHODE

## LED-GREEN 1206_1
designator DS?, comment LED-GREEN
P/N: 139A10020S
footprint LED-1206
pins: ANODE, CATHODE

## LED-GREEN 1206_2
designator DS?, comment LED-GREEN
P/N: 139A10020S
footprint LED-1206
pins: ANODE, CATHODE

## LED-GREEN 1206_2_1
designator DS?, comment LED-GREEN
P/N: 139A10020S
footprint LED-1206
pins: ANODE, CATHODE

## M_0.2 Key B Connector
designator P?, comment M.2 Key B Connector
footprint TBD
pins: 1 CONFIG_3, 2 +3.3V, 3 GND, 4 +3.3V, 5 GND, 6 CARD_PWR_OFF#(1.8V/3.3V), 7 USB_D+, 8 W_DIS1#, 9 USB_D-, 10 GPIO9/DAS/DSS#(3.3V), 11 GND, 20 GPIO5(1.8V), 21 CONFIG_0, 22 GPIO6(1.8V), 23 GPIO_11(1.8V), 24 GPIO7(1.8V), 25 DPR(1.8V), 26 GPIO10(1.8V), 27 GND, 28 GPIO8(1.8V), 29 PERN1/USB3_RXN/SSIC, 30 UIM-RESET, 31 PERP1/USB3_RXP/SSIC, 32 UIM-CLK, 33 GND, 34 UIM-DATA, 35 PETN1/USB3_TXN/SSIC, 36 UIM-PWR, 37 PETP1/USB3_TXP/SSIC, 38 DEVSLP, 39 GND, 40 GPIO0/SMB_CLK(1.8V), 41 PERN0/SATA_RXP, 42 GPIO1/SMB_DATA(1.8V), 43 PERP0/SATA_RXN, 44 GPIO2/ALERT#(1.8V), 45 GND, 46 GPIO3(1.8V), 47 PETN0/SATA_TXN, 48 GPIO4(1.8V), 49 PETP0/SATA_TXP, 50 PERST#, 51 GND, 52 CLKREQ#, 53 REFCLKN, 54 WAKE#, 55 REFCLKP, 56 N/C, 57 GND, 58 N/C, 59 ANTCTL0(1.8V), 60 COEX3, 61 ANTCTL1(1.8V), 62 COEX_TXD(1.8V), 63 ANTCTL2(1.8V), 64 COEX_RXD(1.8V), 65 ANTCTL3(1.8V), 66 SIM DETECT, 67 RESET#(1.8V), 68 SUSCLK, 69 CONFIG_1, 70 +3.3V, 71 GND, 72 +3.3V, 73 GND, 74 +3.3V, 75 CONFIG_2

## M_1.2 Key B Connector
designator P?, comment M.2 Key B Connector
footprint TBD
pins: 1 CONFIG_3, 2 +3.3V, 3 GND, 4 +3.3V, 5 GND, 6 CARD_PWR_OFF#(1.8V/3.3V), 7 USB_D+, 8 W_DIS1#, 9 USB_D-, 10 GPIO9/DAS/DSS#(3.3V), 11 GND, 20 GPIO5(1.8V), 21 CONFIG_0, 22 GPIO6(1.8V), 23 GPIO_11(1.8V), 24 GPIO7(1.8V), 25 DPR(1.8V), 26 GPIO10(1.8V), 27 GND, 28 GPIO8(1.8V), 29 PERN1/USB3_RXN/SSIC, 30 UIM-RESET, 31 PERP1/USB3_RXP/SSIC, 32 UIM-CLK, 33 GND, 34 UIM-DATA, 35 PETN1/USB3_TXN/SSIC, 36 UIM-PWR, 37 PETP1/USB3_TXP/SSIC, 38 DEVSLP, 39 GND, 40 GPIO0/SMB_CLK(1.8V), 41 PERN0/SATA_RXP, 42 GPIO1/SMB_DATA(1.8V), 43 PERP0/SATA_RXN, 44 GPIO2/ALERT#(1.8V), 45 GND, 46 GPIO3(1.8V), 47 PETN0/SATA_TXN, 48 GPIO4(1.8V), 49 PETP0/SATA_TXP, 50 PERST#, 51 GND, 52 CLKREQ#, 53 REFCLKN, 54 WAKE#, 55 REFCLKP, 56 N/C, 57 GND, 58 N/C, 59 ANTCTL0(1.8V), 60 COEX3, 61 ANTCTL1(1.8V), 62 COEX_TXD(1.8V), 63 ANTCTL2(1.8V), 64 COEX_RXD(1.8V), 65 ANTCTL3(1.8V), 66 SIM DETECT, 67 RESET#(1.8V), 68 SUSCLK, 69 CONFIG_1, 70 +3.3V, 71 GND, 72 +3.3V, 73 GND, 74 +3.3V, 75 CONFIG_2, NC1, NC2

## M_2.2 Key B Connector
designator P?, comment M.2 Key B Connector
footprint TBD
pins: 1 CONFIG_3, 2 +3.3V, 3 GND, 4 +3.3V, 5 GND, 6 CARD_PWR_OFF#(1.8V/3.3V), 7 USB_D+, 8 W_DIS1#, 9 USB_D-, 10 GPIO9/DAS/DSS#(3.3V), 11 GND, 20 GPIO5(1.8V), 21 CONFIG_0, 22 GPIO6(1.8V), 23 GPIO_11(1.8V), 24 GPIO7(1.8V), 25 DPR(1.8V), 26 GPIO10(1.8V), 27 GND, 28 GPIO8(1.8V), 29 PERN1/USB3_RXN/SSIC, 30 UIM-RESET, 31 PERP1/USB3_RXP/SSIC, 32 UIM-CLK, 33 GND, 34 UIM-DATA, 35 PETN1/USB3_TXN/SSIC, 36 UIM-PWR, 37 PETP1/USB3_TXP/SSIC, 38 DEVSLP, 39 GND, 40 GPIO0/SMB_CLK(1.8V), 41 PERN0, 42 GPIO1/SMB_DATA(1.8V), 43 PERP0, 44 GPIO2/ALERT#(1.8V), 45 GND, 46 GPIO3(1.8V), 47 PETN0, 48 GPIO4(1.8V), 49 PETP0, 50 PERST#, 51 GND, 52 CLKREQ#, 53 REFCLKN, 54 WAKE#, 55 REFCLKP, 56 N/C, 57 GND, 58 N/C, 59 ANTCTL0(1.8V), 60 COEX3, 61 ANTCTL1(1.8V), 62 COEX_TXD(1.8V), 63 ANTCTL2(1.8V), 64 COEX_RXD(1.8V), 65 ANTCTL3(1.8V), 66 SIM DETECT, 67 RESET#(1.8V), 68 SUSCLK, 69 CONFIG_1, 70 +3.3V, 71 GND, 72 +3.3V, 73 GND, 74 +3.3V, 75 CONFIG_2, NC1, NC2

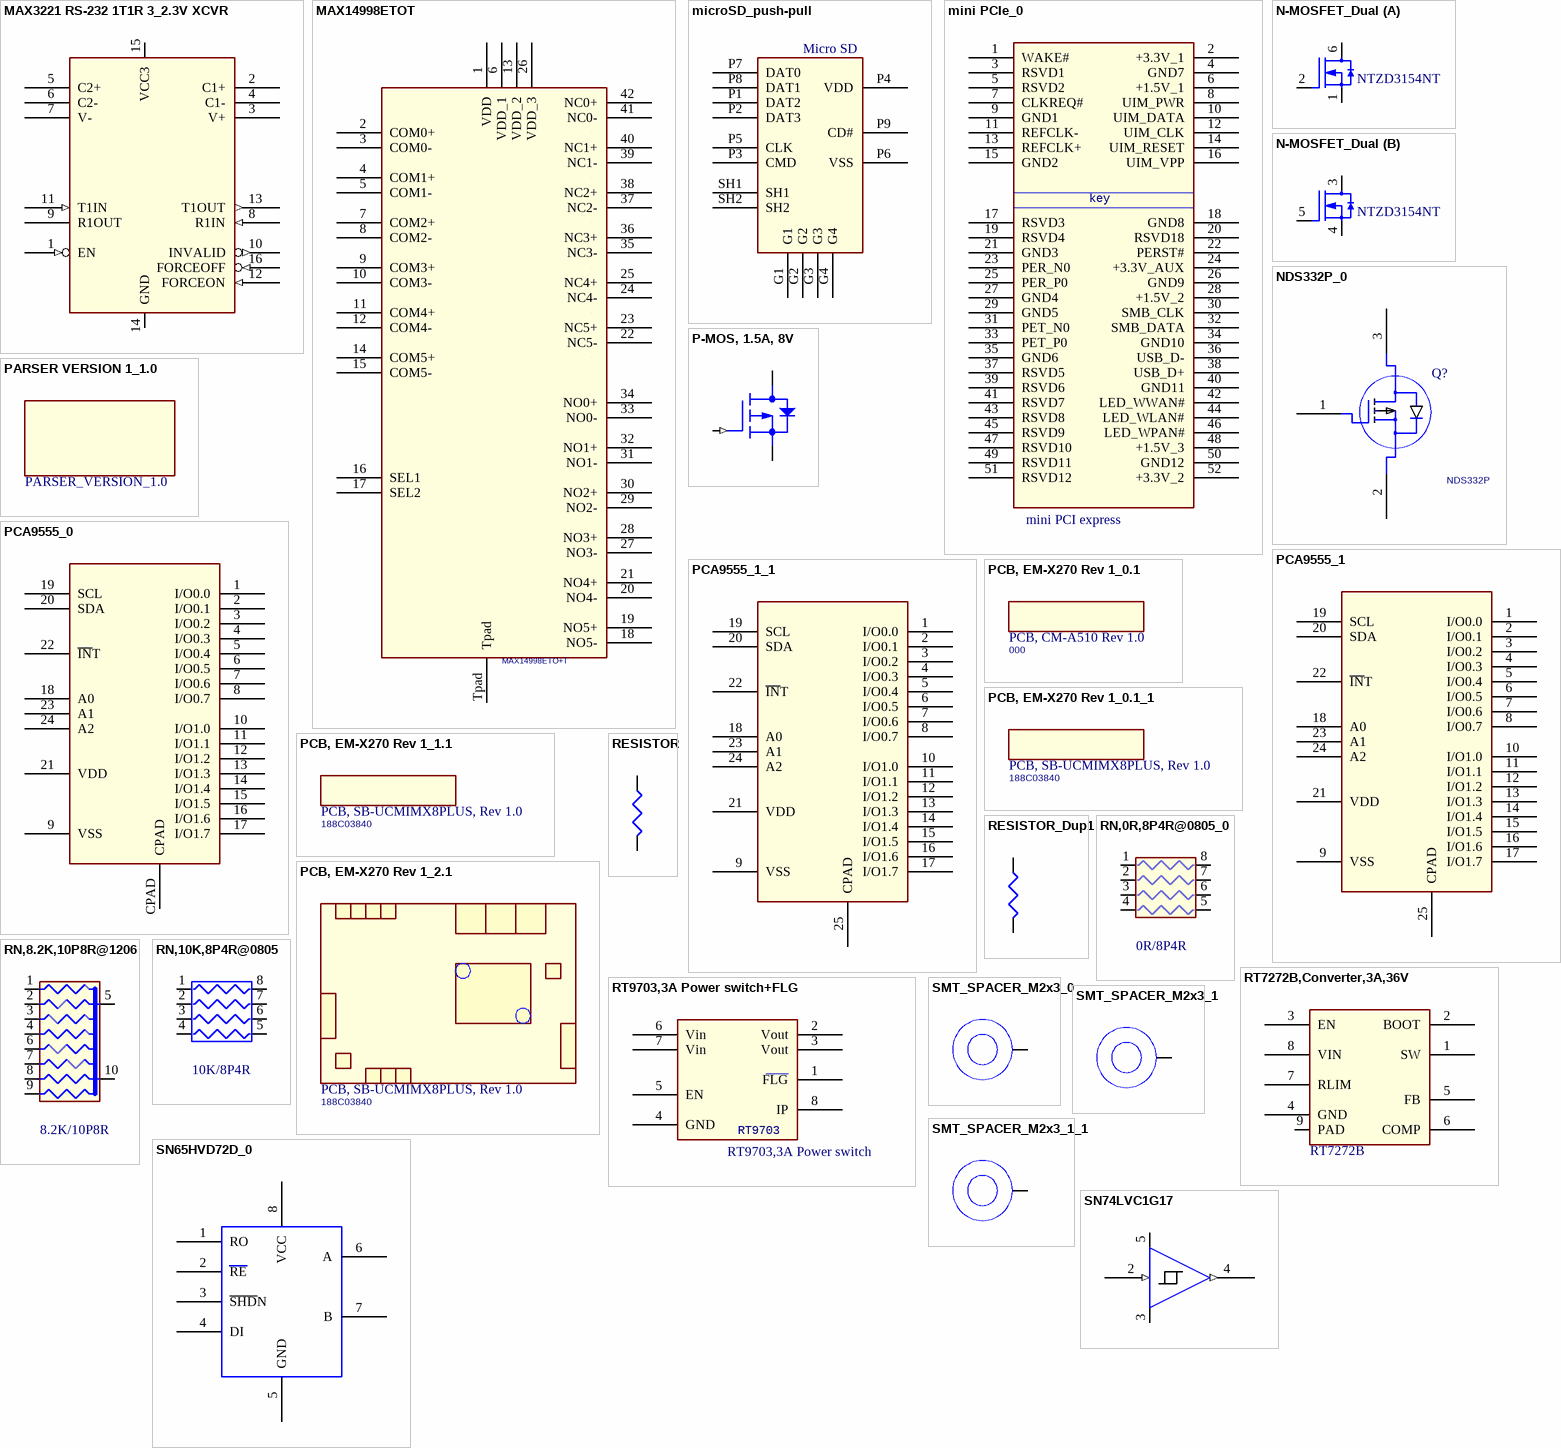
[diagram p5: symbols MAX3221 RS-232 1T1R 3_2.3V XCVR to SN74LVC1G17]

## MAX3221 RS-232 1T1R 3_2.3V XCVR
designator U?
P/N: 116A32210I
footprint SSOP-16
pins: 1 EN (in), 2 C1+, 3 V+, 4 C1-, 5 C2+, 6 C2-, 7 V-, 8 R1IN (in), 9 R1OUT (hiz), 10 INVALID (out), 11 T1IN (in), 12 FORCEON (in), 13 T1OUT (out), 14 GND (power), 15 VCC3 (power), 16 FORCEOFF (in)

## MAX14998ETOT
designator U?  < Value >: MAX14998ETO+T
P/N: 124S10070S; IsHeterogeneous: False; DevicesInView: 1; DeviceDesignator: A; DeviceNumbering: Alpha; PCB Footprint: QFN3.5x9-42; OriginalSymbolOrigin: (30000,10000)
footprint 21-0181B_T423590M-1_MXM
pins: 1 VDD (power), 2 COM0+, 3 COM0-, 4 COM1+, 5 COM1-, 6 VDD_1 (power), 7 COM2+, 8 COM2-, 9 COM3+, 10 COM3-, 11 COM4+, 12 COM4-, 13 VDD_2 (power), 14 COM5+, 15 COM5-, 16 SEL1, 17 SEL2, 18 NO5-, 19 NO5+, 20 NO4-, 21 NO4+, 22 NC5-, 23 NC5+, 24 NC4-, 25 NC4+, 26 VDD_3 (power), 27 NO3-, 28 NO3+, 29 NO2-, 30 NO2+, 31 NO1-, 32 NO1+, 33 NO0-, 34 NO0+, 35 NC3-, 36 NC3+, 37 NC2-, 38 NC2+, 39 NC1-, 40 NC1+, 41 NC0-, 42 NC0+, Tpad

## microSD_push-pull
designator P?, comment Micro SD
P/N: 182K00802S
footprint MicroSD-PP-RA-SM
pins: G1, G2, G3, G4, P1 DAT2, P2 DAT3, P3 CMD, P4 VDD, P5 CLK, P6 VSS, P7 DAT0, P8 DAT1, P9 CD#, SH1, SH2

## mini PCIe_0
designator P?, comment mini PCI express
P/N: 182K05200S
footprint MINIPCIE-4
pins: 1 WAKE#, 2 +3.3V_1, 3 RSVD1, 4 GND7, 5 RSVD2, 6 +1.5V_1, 7 CLKREQ#, 8 UIM_PWR, 9 GND1, 10 UIM_DATA, 11 REFCLK-, 12 UIM_CLK, 13 REFCLK+, 14 UIM_RESET, 15 GND2, 16 UIM_VPP, 17 RSVD3, 18 GND8, 19 RSVD4, 20 RSVD18, 21 GND3, 22 PERST#, 23 PER_N0, 24 +3.3V_AUX, 25 PER_P0, 26 GND9, 27 GND4, 28 +1.5V_2, 29 GND5, 30 SMB_CLK, 31 PET_N0, 32 SMB_DATA, 33 PET_P0, 34 GND10, 35 GND6, 36 USB_D-, 37 RSVD5, 38 USB_D+, 39 RSVD6, 40 GND11, 41 RSVD7, 42 LED_WWAN#, 43 RSVD8, 44 LED_WLAN#, 45 RSVD9, 46 LED_WPAN#, 47 RSVD10, 48 +1.5V_3, 49 RSVD11, 50 GND12, 51 RSVD12, 52 +3.3V_2

## N-MOSFET_Dual
designator U?, comment NTZD3154NT
P/N: 131D03350S
footprint SOT-563-6
part A pins: 1 S, 2 G, 6 D
part B pins: 3 D, 4 S, 5 G

## NDS332P_0
designator Q?, comment NDS332P
P/N: 131D41510S
pins: 1 Gate, 2 Source, 3 Drain

## P-MOS, 1.5A, 8V
designator Q?
P/N: 131D21010S
footprint SOT23
pins: 1 G (in), 2 S, 3 D

## PARSER VERSION 1_1.0
designator ZZ?, comment PARSER_VERSION_1.0
P/N: 188Z10030; CLABCONF0: DNP

## PCA9555_0
designator U?
P/N: 116B95550S
footprint QFN4x4-24
pins: 1 I/O0.0, 2 I/O0.1, 3 I/O0.2, 4 I/O0.3, 5 I/O0.4, 6 I/O0.5, 7 I/O0.6, 8 I/O0.7, 9 VSS, 10 I/O1.0, 11 I/O1.1, 12 I/O1.2, 13 I/O1.3, 14 I/O1.4, 15 I/O1.5, 16 I/O1.6, 17 I/O1.7, 18 A0, 19 SCL, 20 SDA, 21 VDD, 22 ~{IN}T, 23 A1, 24 A2, CPAD

## PCA9555_1
designator U?
P/N: 116B95550S
footprint QFN4x4-24
pins: 1 I/O0.0, 2 I/O0.1, 3 I/O0.2, 4 I/O0.3, 5 I/O0.4, 6 I/O0.5, 7 I/O0.6, 8 I/O0.7, 9 VSS, 10 I/O1.0, 11 I/O1.1, 12 I/O1.2, 13 I/O1.3, 14 I/O1.4, 15 I/O1.5, 16 I/O1.6, 17 I/O1.7, 18 A0, 19 SCL, 20 SDA, 21 VDD, 22 ~{IN}T, 23 A1, 24 A2, 25 CPAD

## PCA9555_1_1
designator U?
P/N: 116B95550S
footprint QFN4x4-24
pins: 1 I/O0.0, 2 I/O0.1, 3 I/O0.2, 4 I/O0.3, 5 I/O0.4, 6 I/O0.5, 7 I/O0.6, 8 I/O0.7, 9 VSS, 10 I/O1.0, 11 I/O1.1, 12 I/O1.2, 13 I/O1.3, 14 I/O1.4, 15 I/O1.5, 16 I/O1.6, 17 I/O1.7, 18 A0, 19 SCL, 20 SDA, 21 VDD, 22 ~{IN}T, 23 A1, 24 A2, 25 CPAD

## PCB, EM-X270 Rev 1_0.1
designator PCB?, comment PCB, CM-A510 Rev 1.0  P/N: 000

## PCB, EM-X270 Rev 1_0.1_1
designator PCB?, comment PCB, SB-UCMIMX8PLUS, Rev 1.0  P/N: 188C03840

## PCB, EM-X270 Rev 1_1.1
designator PCB?, comment PCB, SB-UCMIMX8PLUS, Rev 1.0  P/N: 188C03840

## PCB, EM-X270 Rev 1_2.1
designator PCB?, comment PCB, SB-UCMIMX8PLUS, Rev 1.0  P/N: 188C03840

## RESISTOR
designator R?
pins: 1, 2

## RESISTOR_Dup1
designator R?
pins: 1, 2

## RN,0R,8P4R@0805_0
designator RN?, comment 0R/8P4R
P/N: 163K04000S
footprint RESNET8P0805
pins: 1 RA1, 2 RB1, 3 RC1, 4 RD1, 5 RD2, 6 RC2, 7 RB2, 8 RA2

## RN,8.2K,10P8R@1206
designator RN?, comment 8.2K/10P8R
P/N: 163I08822S
footprint RESNET10P1206
pins: 1 R1, 2 R2, 3 R3, 4 R4, 5 COM1, 6 R5, 7 R6, 8 R7, 9 R8, 10 COM2

## RN,10K,8P4R@0805
designator RN?, comment 10K/8P4R
P/N: 163K04103S
footprint RESNET8P0805
pins: 1 RA1, 2 RB1, 3 RC1, 4 RD1, 5 RD2, 6 RC2, 7 RB2, 8 RA2

## RT7272B,Converter,3A,36V
designator U?, comment RT7272B
footprint TBD
pins: 1 SW, 2 BOOT, 3 EN, 4 GND, 5 FB, 6 COMP, 7 RLIM, 8 VIN, 9 PAD

## RT9703,3A Power switch+FLG
designator U?, comment RT9703,3A Power switch
P/N: 124S97030S
footprint SO-8-150
pins: 1 FLG, 2 Vout, 3 Vout, 4 GND, 5 EN, 6 Vin, 7 Vin, 8 IP

## SMT_SPACER_M2x3_0
designator SP?
P/N: 383B52520S
footprint MINIPCIE-4-Spacer
pins: NC

## SMT_SPACER_M2x3_1
designator SP?
P/N: 383B52520S
footprint MINIPCIE-4-Spacer
pins: NC 1

## SMT_SPACER_M2x3_1_1
designator SP?
P/N: 383B52520S
footprint MINIPCIE-4-Spacer
pins: NC 1

## SN65HVD72D_0
designator U?
PN: No Compulab PN
pins: 1 RO, 2 RE, 3 ~{SHD}N, 4 DI, 5 GND, 6 A, 7 B, 8 VCC

## SN74LVC1G17
designator U?
pins: 2 A (in), 3 GND, 4 Y (out), 5 VCC

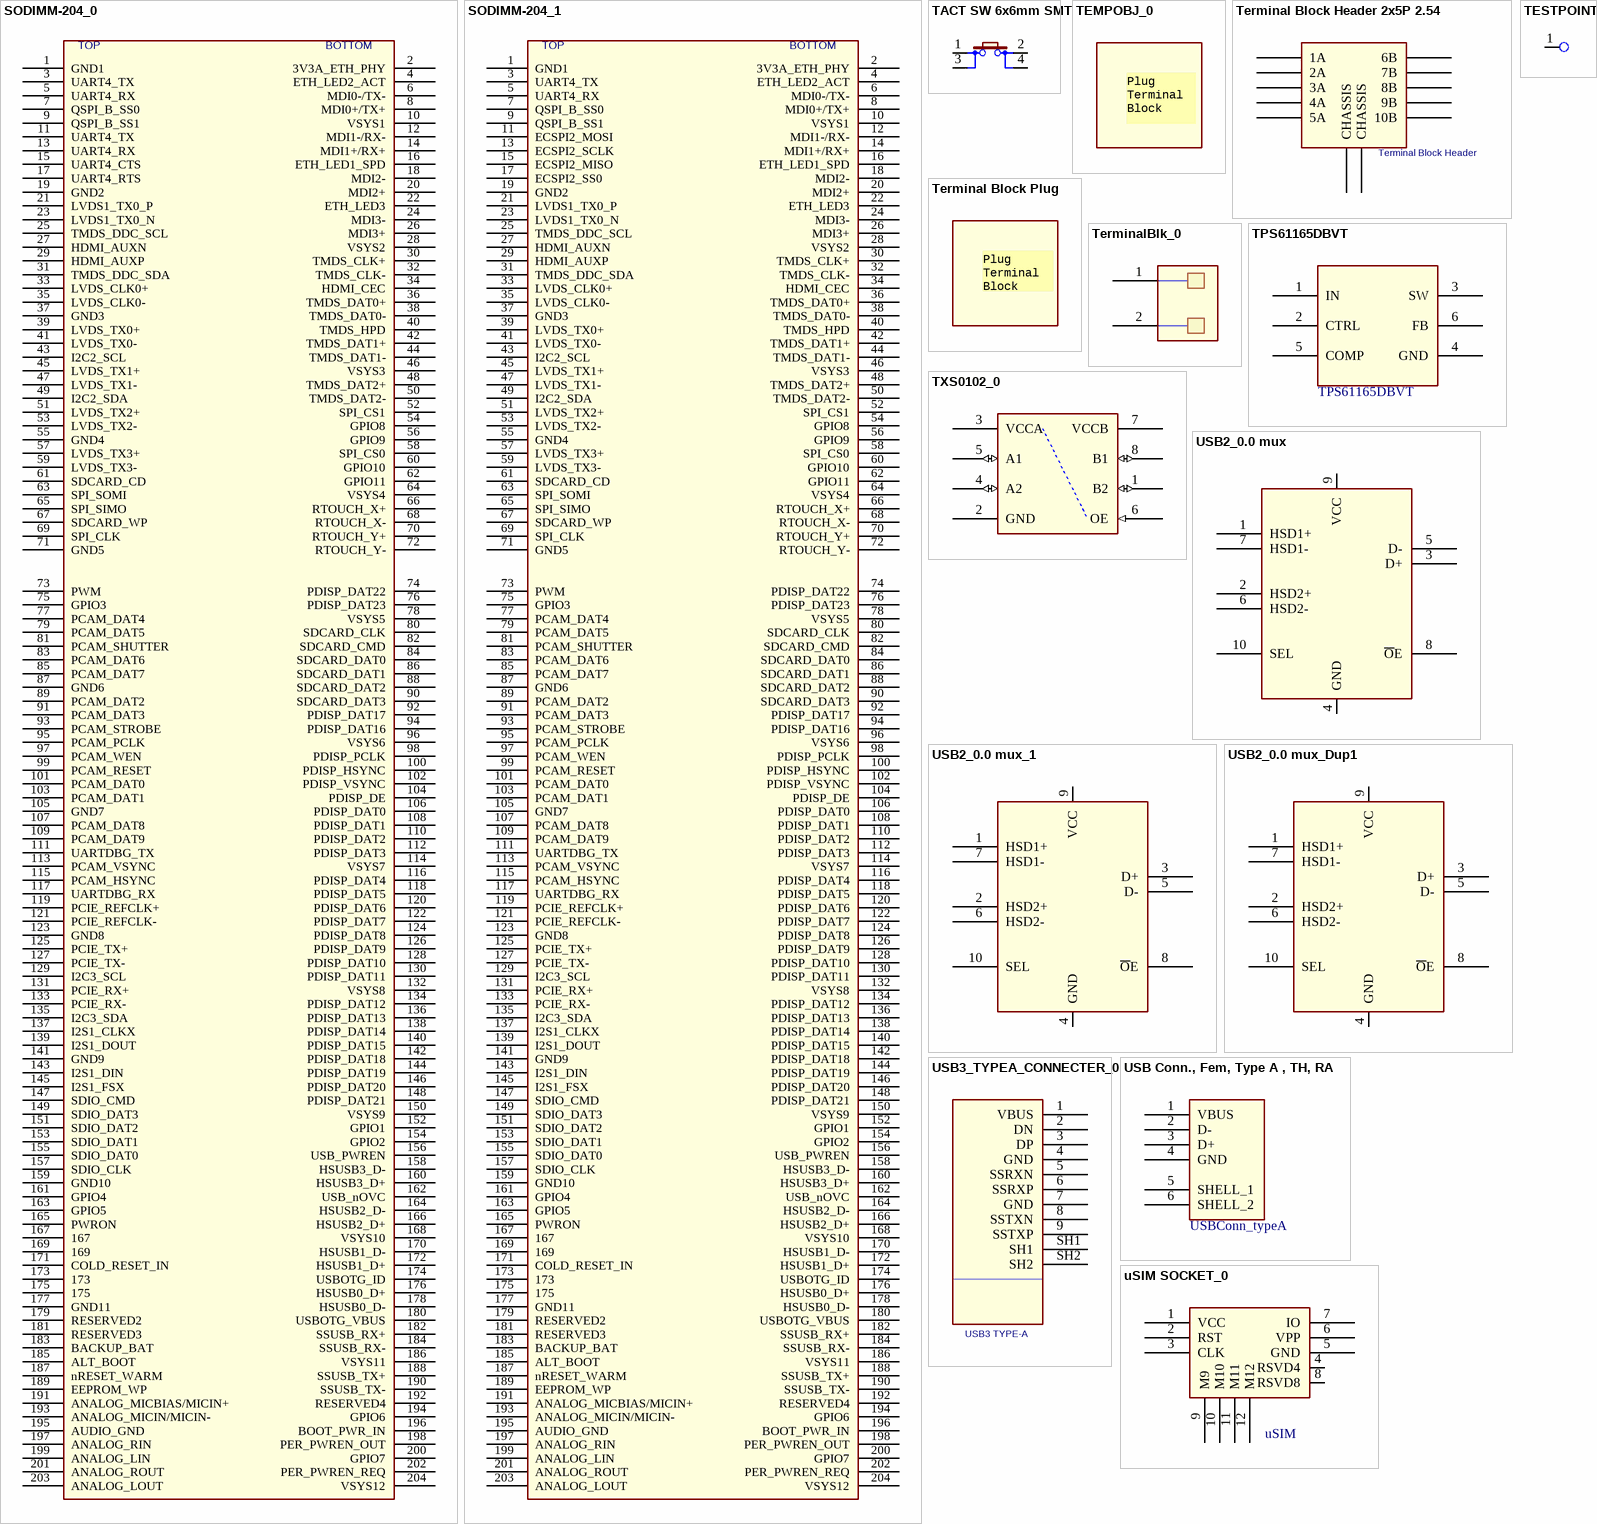
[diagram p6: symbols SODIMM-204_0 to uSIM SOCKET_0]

## SODIMM-204_0
designator P?
footprint 190I20400S
pins: 1 GND1, 2 3V3A_ETH_PHY, 3 UART4_TX, 4 ETH_LED2_ACT, 5 UART4_RX, 6 MDI0-/TX-, 7 QSPI_B_SS0, 8 MDI0+/TX+, 9 QSPI_B_SS1, 10 VSYS1, 11 UART4_TX, 12 MDI1-/RX-, 13 UART4_RX, 14 MDI1+/RX+, 15 UART4_CTS, 16 ETH_LED1_SPD, 17 UART4_RTS, 18 MDI2-, 19 GND2, 20 MDI2+, 21 LVDS1_TX0_P, 22 ETH_LED3, 23 LVDS1_TX0_N, 24 MDI3-, 25 TMDS_DDC_SCL, 26 MDI3+, 27 HDMI_AUXN, 28 VSYS2, 29 HDMI_AUXP, 30 TMDS_CLK+, 31 TMDS_DDC_SDA, 32 TMDS_CLK-, 33 LVDS_CLK0+, 34 HDMI_CEC, 35 LVDS_CLK0-, 36 TMDS_DAT0+, 37 GND3, 38 TMDS_DAT0-, 39 LVDS_TX0+, 40 TMDS_HPD, 41 LVDS_TX0-, 42 TMDS_DAT1+, 43 I2C2_SCL, 44 TMDS_DAT1-, 45 LVDS_TX1+, 46 VSYS3, 47 LVDS_TX1-, 48 TMDS_DAT2+, 49 I2C2_SDA, 50 TMDS_DAT2-, 51 LVDS_TX2+, 52 SPI_CS1, 53 LVDS_TX2-, 54 GPIO8, 55 GND4, 56 GPIO9, 57 LVDS_TX3+, 58 SPI_CS0, 59 LVDS_TX3-, 60 GPIO10, 61 SDCARD_CD, 62 GPIO11, 63 SPI_SOMI, 64 VSYS4, 65 SPI_SIMO, 66 RTOUCH_X+, 67 SDCARD_WP, 68 RTOUCH_X-, 69 SPI_CLK, 70 RTOUCH_Y+, 71 GND5, 72 RTOUCH_Y-, 73 PWM, 74 PDISP_DAT22, 75 GPIO3, 76 PDISP_DAT23, 77 PCAM_DAT4, 78 VSYS5, 79 PCAM_DAT5, 80 SDCARD_CLK, 81 PCAM_SHUTTER, 82 SDCARD_CMD, 83 PCAM_DAT6, 84 SDCARD_DAT0, 85 PCAM_DAT7, 86 SDCARD_DAT1, 87 GND6, 88 SDCARD_DAT2, 89 PCAM_DAT2, 90 SDCARD_DAT3, 91 PCAM_DAT3, 92 PDISP_DAT17, 93 PCAM_STROBE, 94 PDISP_DAT16, 95 PCAM_PCLK, 96 VSYS6, 97 PCAM_WEN, 98 PDISP_PCLK, 99 PCAM_RESET, 100 PDISP_HSYNC, 101 PCAM_DAT0, 102 PDISP_VSYNC, 103 PCAM_DAT1, 104 PDISP_DE, 105 GND7, 106 PDISP_DAT0, 107 PCAM_DAT8, 108 PDISP_DAT1, 109 PCAM_DAT9, 110 PDISP_DAT2, 111 UARTDBG_TX, 112 PDISP_DAT3, 113 PCAM_VSYNC, 114 VSYS7, 115 PCAM_HSYNC, 116 PDISP_DAT4, 117 UARTDBG_RX, 118 PDISP_DAT5, 119 PCIE_REFCLK+, 120 PDISP_DAT6, 121 PCIE_REFCLK-, 122 PDISP_DAT7, 123 GND8, 124 PDISP_DAT8, 125 PCIE_TX+, 126 PDISP_DAT9, 127 PCIE_TX-, 128 PDISP_DAT10, 129 I2C3_SCL, 130 PDISP_DAT11, 131 PCIE_RX+, 132 VSYS8, 133 PCIE_RX-, 134 PDISP_DAT12, 135 I2C3_SDA, 136 PDISP_DAT13, 137 I2S1_CLKX, 138 PDISP_DAT14, 139 I2S1_DOUT, 140 PDISP_DAT15, 141 GND9, 142 PDISP_DAT18, 143 I2S1_DIN, 144 PDISP_DAT19, 145 I2S1_FSX, 146 PDISP_DAT20, 147 SDIO_CMD, 148 PDISP_DAT21, 149 SDIO_DAT3, 150 VSYS9, 151 SDIO_DAT2, 152 GPIO1, 153 SDIO_DAT1, 154 GPIO2, 155 SDIO_DAT0, 156 USB_PWREN, 157 SDIO_CLK, 158 HSUSB3_D-, 159 GND10, 160 HSUSB3_D+, 161 GPIO4, 162 USB_nOVC, 163 GPIO5, 164 HSUSB2_D-, 165 PWRON, 166 HSUSB2_D+, 167, 168 VSYS10, 169, 170 HSUSB1_D-, 171 COLD_RESET_IN, 172 HSUSB1_D+, 173, 174 USBOTG_ID, 175, 176 HSUSB0_D+, 177 GND11, 178 HSUSB0_D-, 179 RESERVED2, 180 USBOTG_VBUS, 181 RESERVED3, 182 SSUSB_RX+, 183 BACKUP_BAT, 184 SSUSB_RX-, 185 ALT_BOOT, 186 VSYS11, 187 nRESET_WARM, 188 SSUSB_TX+, 189 EEPROM_WP, 190 SSUSB_TX-, 191 ANALOG_MICBIAS/MICIN+, 192 RESERVED4, 193 ANALOG_MICIN/MICIN-, 194 GPIO6, 195 AUDIO_GND, 196 BOOT_PWR_IN, 197 ANALOG_RIN, 198 PER_PWREN_OUT, 199 ANALOG_LIN, 200 GPIO7, 201 ANALOG_ROUT, 202 PER_PWREN_REQ, 203 ANALOG_LOUT, 204 VSYS12

## SODIMM-204_1
designator P?
footprint 190I20400S
pins: 1 GND1, 2 3V3A_ETH_PHY, 3 UART4_TX, 4 ETH_LED2_ACT, 5 UART4_RX, 6 MDI0-/TX-, 7 QSPI_B_SS0, 8 MDI0+/TX+, 9 QSPI_B_SS1, 10 VSYS1, 11 ECSPI2_MOSI, 12 MDI1-/RX-, 13 ECSPI2_SCLK, 14 MDI1+/RX+, 15 ECSPI2_MISO, 16 ETH_LED1_SPD, 17 ECSPI2_SS0, 18 MDI2-, 19 GND2, 20 MDI2+, 21 LVDS1_TX0_P, 22 ETH_LED3, 23 LVDS1_TX0_N, 24 MDI3-, 25 TMDS_DDC_SCL, 26 MDI3+, 27 HDMI_AUXN, 28 VSYS2, 29 HDMI_AUXP, 30 TMDS_CLK+, 31 TMDS_DDC_SDA, 32 TMDS_CLK-, 33 LVDS_CLK0+, 34 HDMI_CEC, 35 LVDS_CLK0-, 36 TMDS_DAT0+, 37 GND3, 38 TMDS_DAT0-, 39 LVDS_TX0+, 40 TMDS_HPD, 41 LVDS_TX0-, 42 TMDS_DAT1+, 43 I2C2_SCL, 44 TMDS_DAT1-, 45 LVDS_TX1+, 46 VSYS3, 47 LVDS_TX1-, 48 TMDS_DAT2+, 49 I2C2_SDA, 50 TMDS_DAT2-, 51 LVDS_TX2+, 52 SPI_CS1, 53 LVDS_TX2-, 54 GPIO8, 55 GND4, 56 GPIO9, 57 LVDS_TX3+, 58 SPI_CS0, 59 LVDS_TX3-, 60 GPIO10, 61 SDCARD_CD, 62 GPIO11, 63 SPI_SOMI, 64 VSYS4, 65 SPI_SIMO, 66 RTOUCH_X+, 67 SDCARD_WP, 68 RTOUCH_X-, 69 SPI_CLK, 70 RTOUCH_Y+, 71 GND5, 72 RTOUCH_Y-, 73 PWM, 74 PDISP_DAT22, 75 GPIO3, 76 PDISP_DAT23, 77 PCAM_DAT4, 78 VSYS5, 79 PCAM_DAT5, 80 SDCARD_CLK, 81 PCAM_SHUTTER, 82 SDCARD_CMD, 83 PCAM_DAT6, 84 SDCARD_DAT0, 85 PCAM_DAT7, 86 SDCARD_DAT1, 87 GND6, 88 SDCARD_DAT2, 89 PCAM_DAT2, 90 SDCARD_DAT3, 91 PCAM_DAT3, 92 PDISP_DAT17, 93 PCAM_STROBE, 94 PDISP_DAT16, 95 PCAM_PCLK, 96 VSYS6, 97 PCAM_WEN, 98 PDISP_PCLK, 99 PCAM_RESET, 100 PDISP_HSYNC, 101 PCAM_DAT0, 102 PDISP_VSYNC, 103 PCAM_DAT1, 104 PDISP_DE, 105 GND7, 106 PDISP_DAT0, 107 PCAM_DAT8, 108 PDISP_DAT1, 109 PCAM_DAT9, 110 PDISP_DAT2, 111 UARTDBG_TX, 112 PDISP_DAT3, 113 PCAM_VSYNC, 114 VSYS7, 115 PCAM_HSYNC, 116 PDISP_DAT4, 117 UARTDBG_RX, 118 PDISP_DAT5, 119 PCIE_REFCLK+, 120 PDISP_DAT6, 121 PCIE_REFCLK-, 122 PDISP_DAT7, 123 GND8, 124 PDISP_DAT8, 125 PCIE_TX+, 126 PDISP_DAT9, 127 PCIE_TX-, 128 PDISP_DAT10, 129 I2C3_SCL, 130 PDISP_DAT11, 131 PCIE_RX+, 132 VSYS8, 133 PCIE_RX-, 134 PDISP_DAT12, 135 I2C3_SDA, 136 PDISP_DAT13, 137 I2S1_CLKX, 138 PDISP_DAT14, 139 I2S1_DOUT, 140 PDISP_DAT15, 141 GND9, 142 PDISP_DAT18, 143 I2S1_DIN, 144 PDISP_DAT19, 145 I2S1_FSX, 146 PDISP_DAT20, 147 SDIO_CMD, 148 PDISP_DAT21, 149 SDIO_DAT3, 150 VSYS9, 151 SDIO_DAT2, 152 GPIO1, 153 SDIO_DAT1, 154 GPIO2, 155 SDIO_DAT0, 156 USB_PWREN, 157 SDIO_CLK, 158 HSUSB3_D-, 159 GND10, 160 HSUSB3_D+, 161 GPIO4, 162 USB_nOVC, 163 GPIO5, 164 HSUSB2_D-, 165 PWRON, 166 HSUSB2_D+, 167, 168 VSYS10, 169, 170 HSUSB1_D-, 171 COLD_RESET_IN, 172 HSUSB1_D+, 173, 174 USBOTG_ID, 175, 176 HSUSB0_D+, 177 GND11, 178 HSUSB0_D-, 179 RESERVED2, 180 USBOTG_VBUS, 181 RESERVED3, 182 SSUSB_RX+, 183 BACKUP_BAT, 184 SSUSB_RX-, 185 ALT_BOOT, 186 VSYS11, 187 nRESET_WARM, 188 SSUSB_TX+, 189 EEPROM_WP, 190 SSUSB_TX-, 191 ANALOG_MICBIAS/MICIN+, 192 RESERVED4, 193 ANALOG_MICIN/MICIN-, 194 GPIO6, 195 AUDIO_GND, 196 BOOT_PWR_IN, 197 ANALOG_RIN, 198 PER_PWREN_OUT, 199 ANALOG_LIN, 200 GPIO7, 201 ANALOG_ROUT, 202 PER_PWREN_REQ, 203 ANALOG_LOUT, 204 VSYS12

## TACT SW 6x6mm SMT
designator SW?, comment PushB  (value not drawn)
P/N: 170B00001S
footprint TACTSW6x6SM
pins: 1, 2, 3, 4

## TEMPOBJ_0
designator J?

## Terminal Block Header 2x5P 2.54
designator J?, comment Terminal Block Header
P/N: 178B01000
footprint TB2.54mmRA-2x5P
pins: 1 1A, 2 2A, 3 3A, 4 4A, 5 5A, 6 6B, 7 7B, 8 8B, 9 9B, 10 10B, CHASSIS, CHASSIS

## Terminal Block Plug
designator J?

## TerminalBlk_0
designator P?
P/N: 178A00200
footprint TB3.5mmRA-2P
pins: 1, 2

## TESTPOINT
designator TP?  (value not drawn)
footprint TESTPOINT
pins: 1

## TPS61165DBVT
designator U?
P/N: 123C20000S
footprint SOT23-6
pins: 1 IN, 2 CTRL, 3 SW, 4 GND, 5 COMP, 6 FB

## TXS0102_0
designator U?
footprint R-PDSO-G8
pins: 1 B2 (io), 2 GND, 3 VCCA, 4 A2 (io), 5 A1 (io), 6 OE (in), 7 VCCB, 8 B1 (io)

## USB2_0.0 mux
designator U?
pins: 1 HSD1+, 2 HSD2+, 3 D+, 4 GND, 5 D-, 6 HSD2-, 7 HSD1-, 8 ~{O}E, 9 VCC, 10 SEL

## USB2_0.0 mux_1
designator U?
pins: 1 HSD1+, 2 HSD2+, 3 D+, 4 GND, 5 D-, 6 HSD2-, 7 HSD1-, 8 ~{O}E, 9 VCC, 10 SEL

## USB2_0.0 mux_Dup1
designator U?
pins: 1 HSD1+, 2 HSD2+, 3 D+, 4 GND, 5 D-, 6 HSD2-, 7 HSD1-, 8 ~{O}E, 9 VCC, 10 SEL

## USB3_TYPEA_CONNECTER_0
designator J?, comment USB3 TYPE-A
OriginalSymbolOrigin: (0,0); P/N: 180K00902S
footprint USB3-A-SM
pins: 1 VBUS, 2 DN, 3 DP, 4 GND (power), 5 SSRXN, 6 SSRXP, 7 GND (power), 8 SSTXN, 9 SSTXP, SH1, SH2

## USB Conn., Fem, Type A , TH, RA
designator P?, comment USBConn_typeA
P/N: 180K00400S
pins: 1 VBUS, 2 D-, 3 D+, 4 GND, 5 SHELL_1, 6 SHELL_2

## uSIM SOCKET_0
designator U?, comment uSIM
P/N: 190I00601S
footprint SKT-MicroSIM6-SM
pins: 1 VCC, 2 RST, 3 CLK, 4 RSVD4, 5 GND, 6 VPP, 7 IO, 8 RSVD8, 9 M9, 10 M10, 11 M11, 12 M12

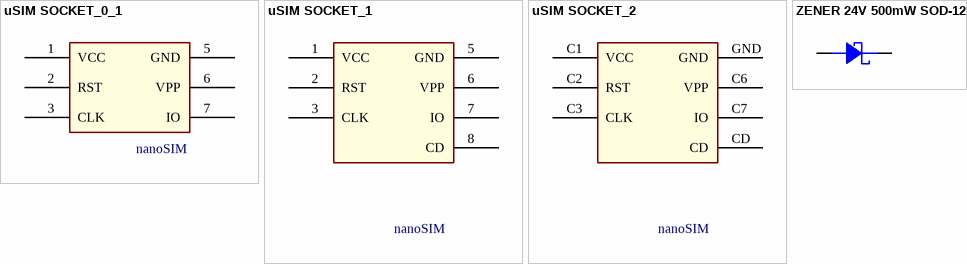
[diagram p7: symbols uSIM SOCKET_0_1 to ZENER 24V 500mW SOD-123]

## uSIM SOCKET_0_1
designator U?, comment nanoSIM
P/N: 190I00601S
footprint SKT-MicroSIM6-SM
pins: 1 VCC, 2 RST, 3 CLK, 5 GND, 6 VPP, 7 IO

## uSIM SOCKET_1
designator U?, comment nanoSIM
P/N: 190I00601S
footprint SKT-MicroSIM6-SM
pins: 1 VCC, 2 RST, 3 CLK, 5 GND, 6 VPP, 7 IO, 8 CD

## uSIM SOCKET_2
designator U?, comment nanoSIM
P/N: 190I00601S
footprint SKT-MicroSIM6-SM
pins: C1 VCC, C2 RST, C3 CLK, C6 VPP, C7 IO, CD, GND

## ZENER 24V 500mW SOD-123
designator D?
P/N: 130B24000S
footprint SOD-123
pins: 1 CATHODE, 2 ANODE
